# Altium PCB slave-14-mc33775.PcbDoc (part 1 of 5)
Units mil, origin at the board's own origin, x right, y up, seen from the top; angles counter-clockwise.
Board outline 6299.21 x 3937.01 mil, 6 copper layers (Top Copper, Supply, Signal Layer 1, Signal Layer 2, GND, Bot Copper), stack 69.773 mil thick; 428 components, 213 nets, 1149 pads, 1672 vias.
Unrouted connection lines stored in the file: 1.
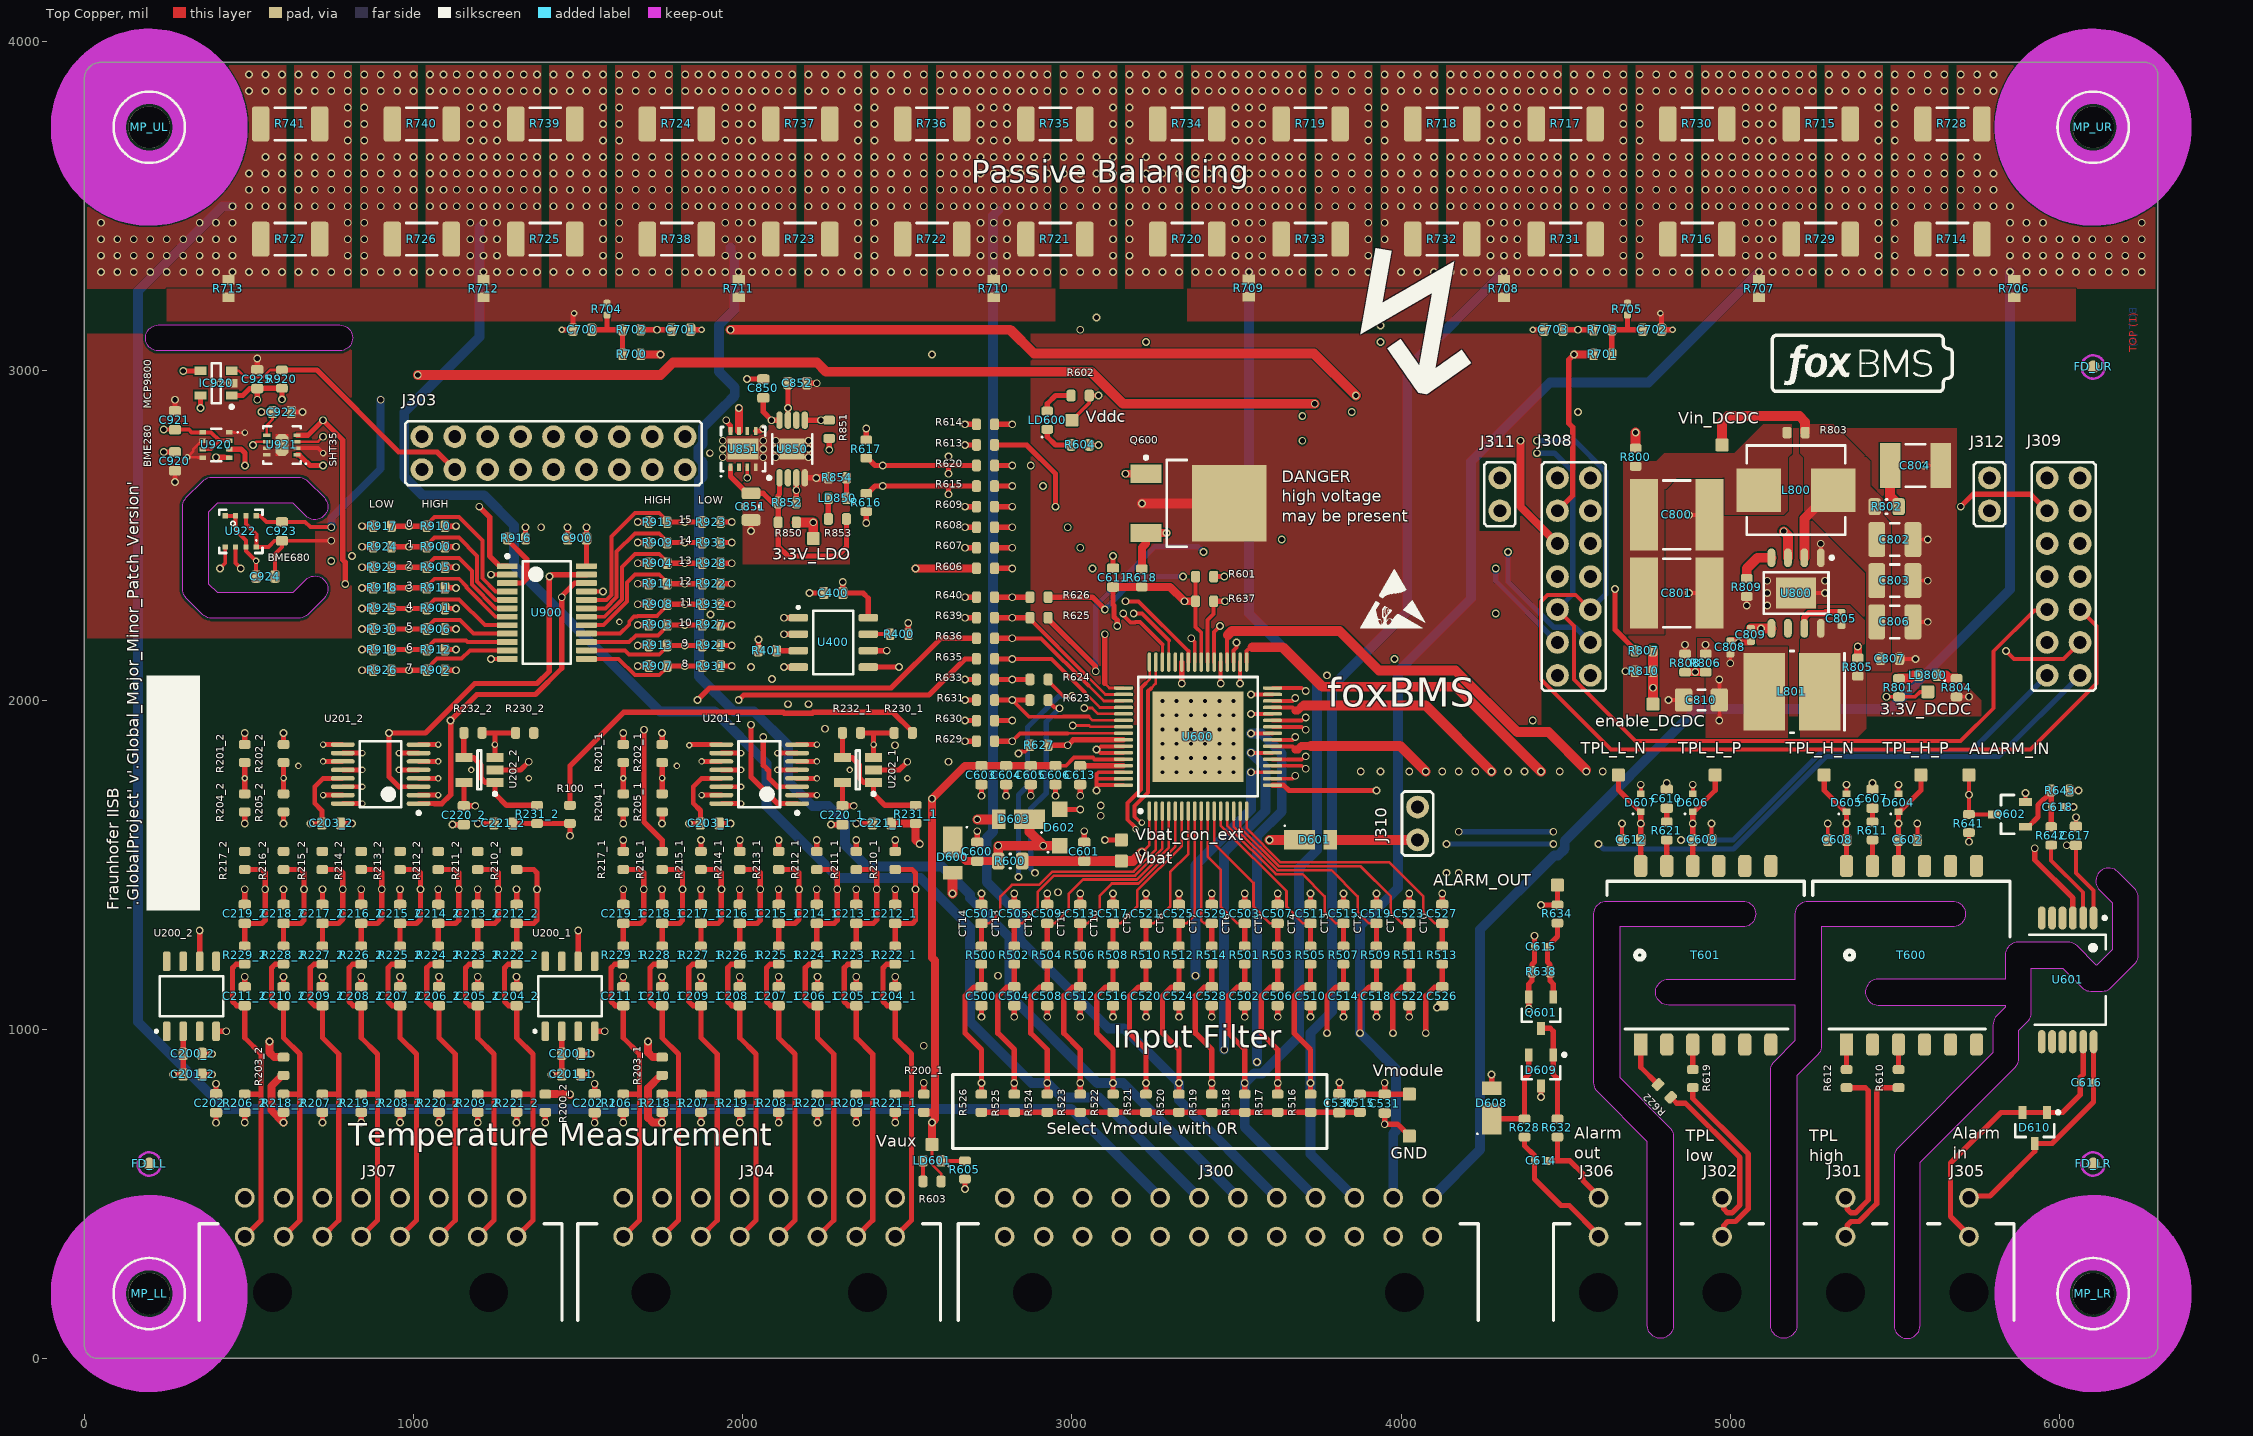
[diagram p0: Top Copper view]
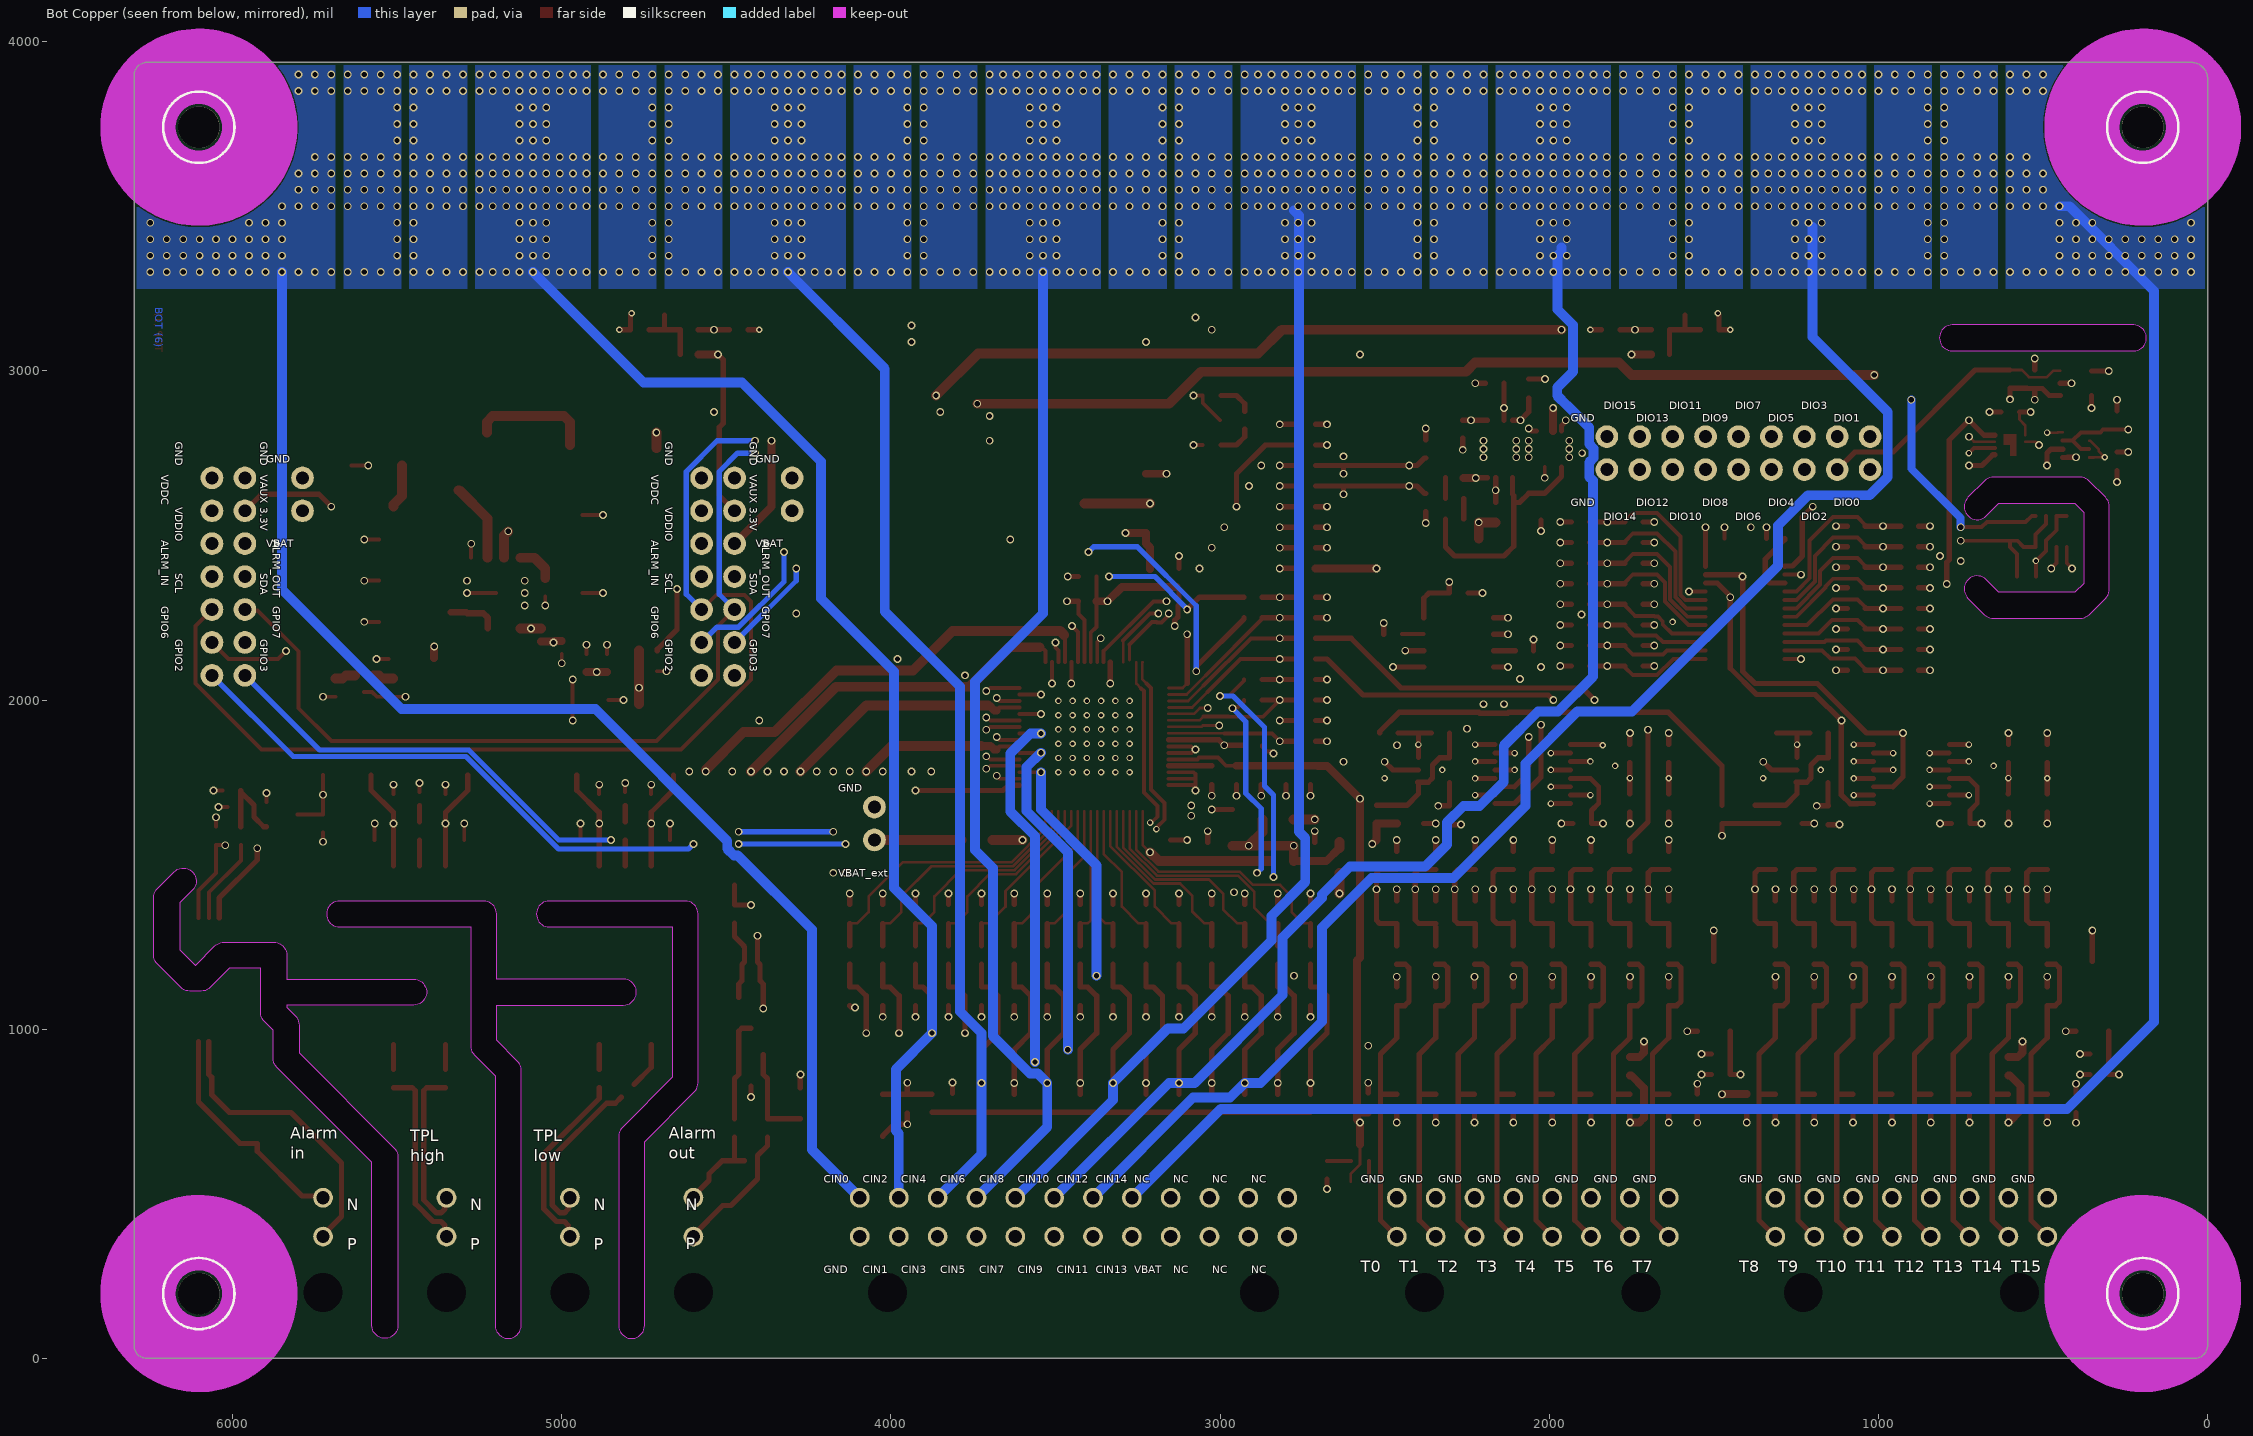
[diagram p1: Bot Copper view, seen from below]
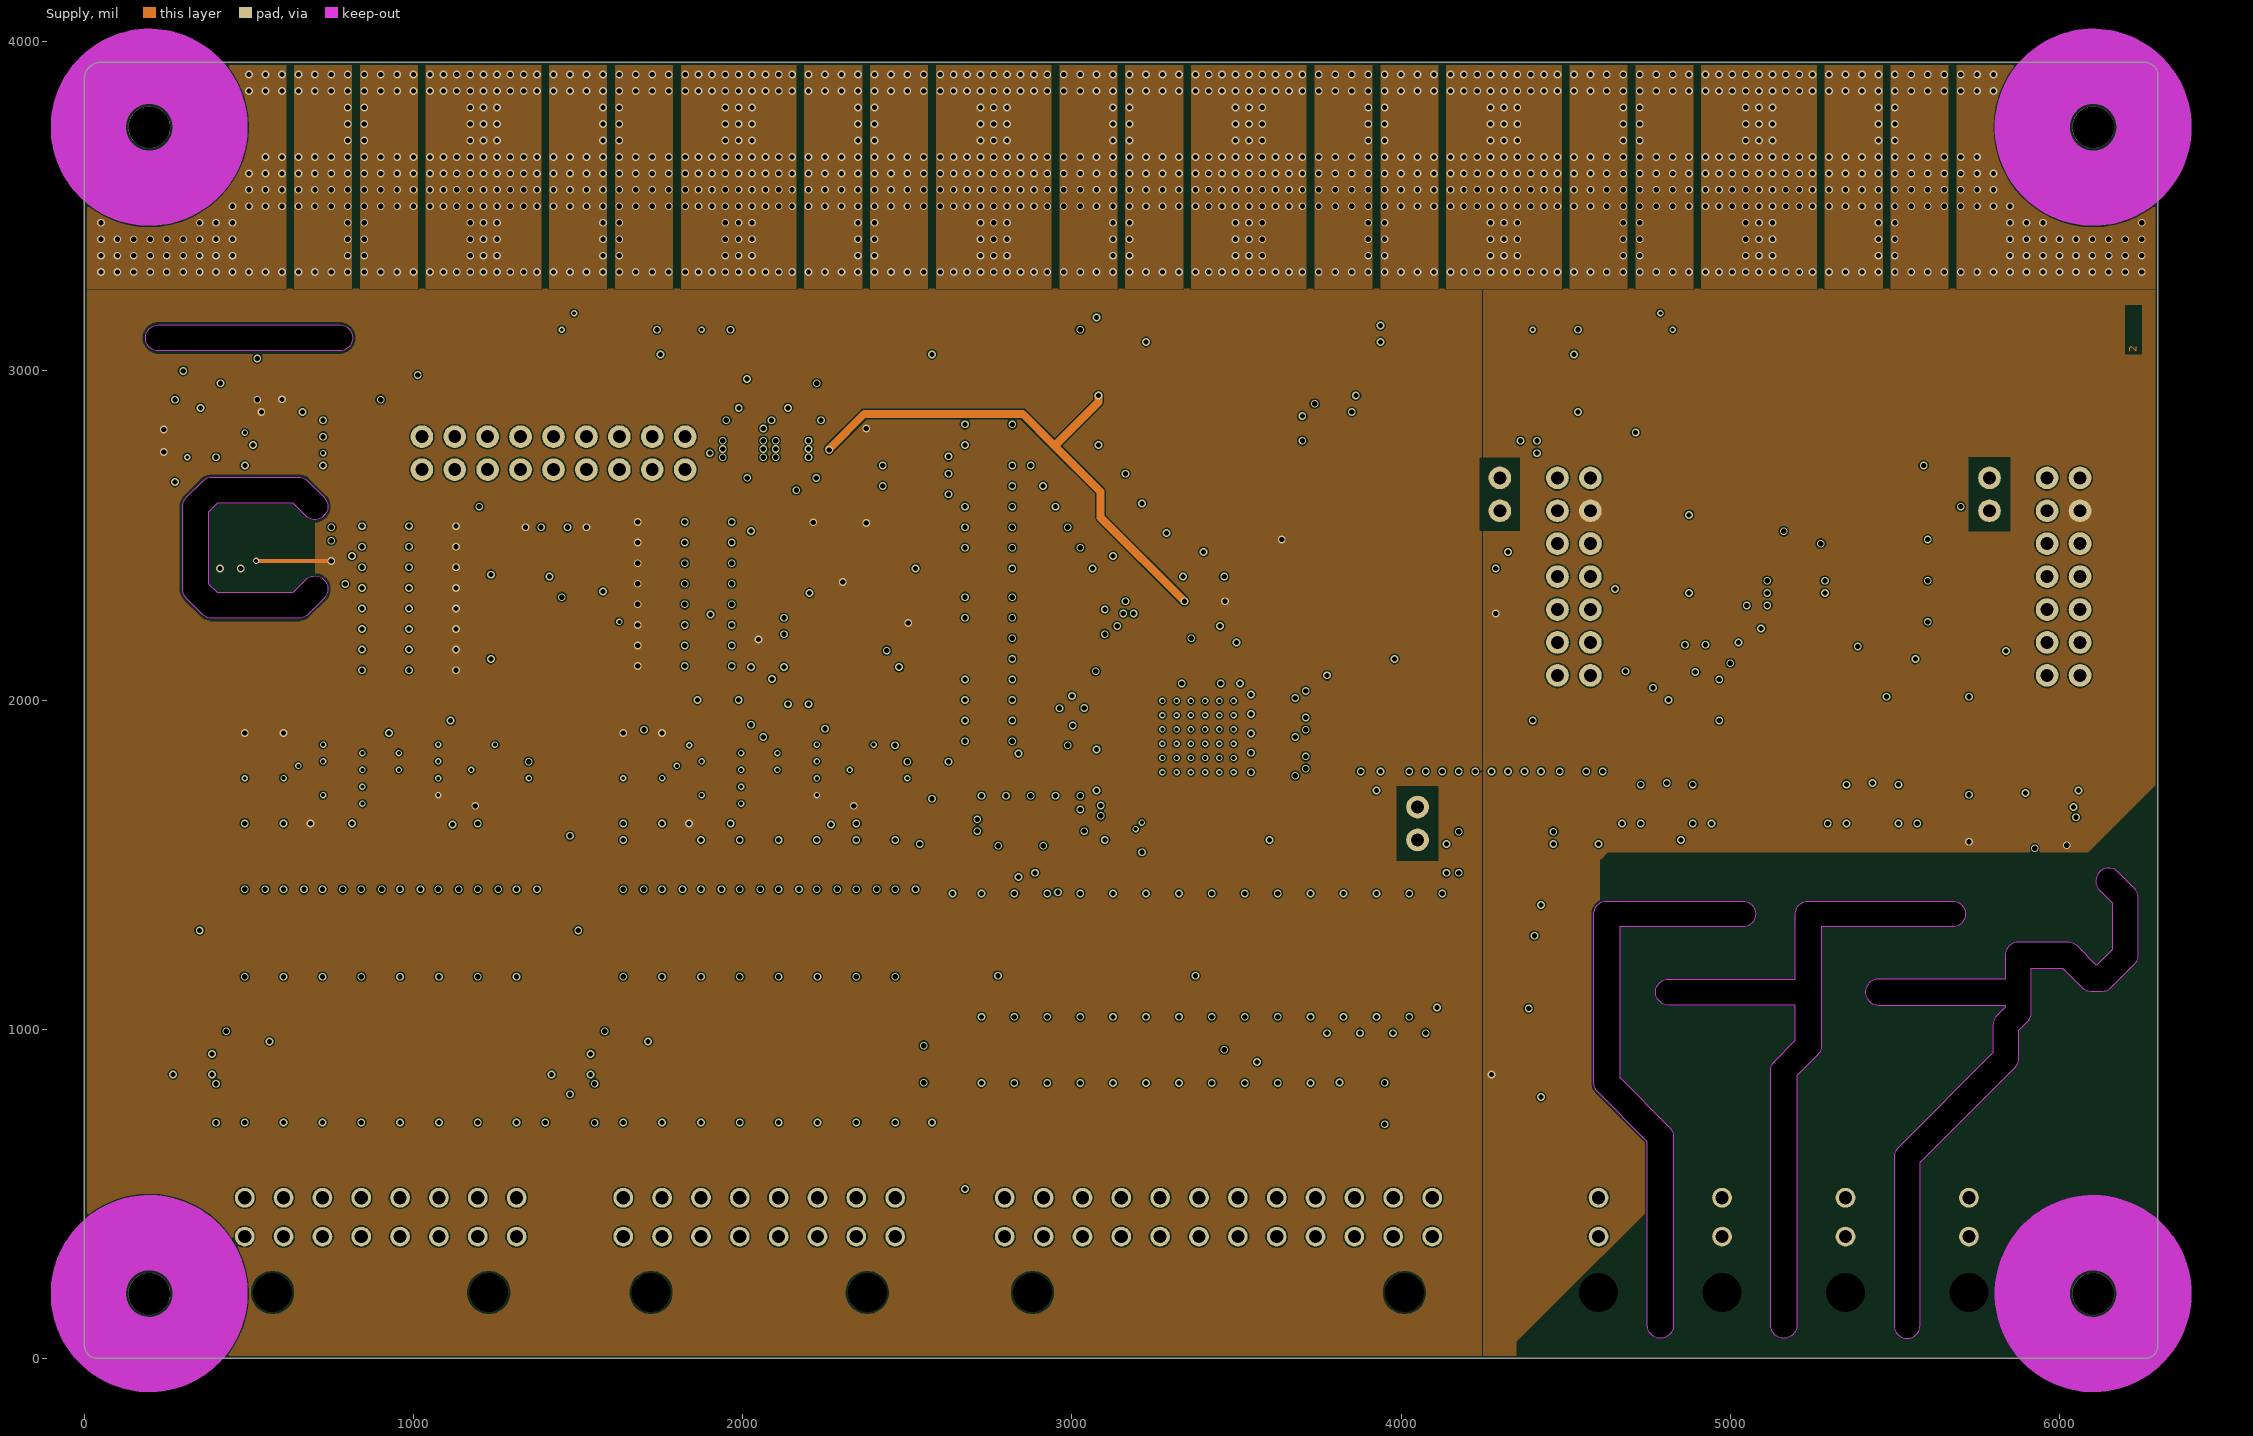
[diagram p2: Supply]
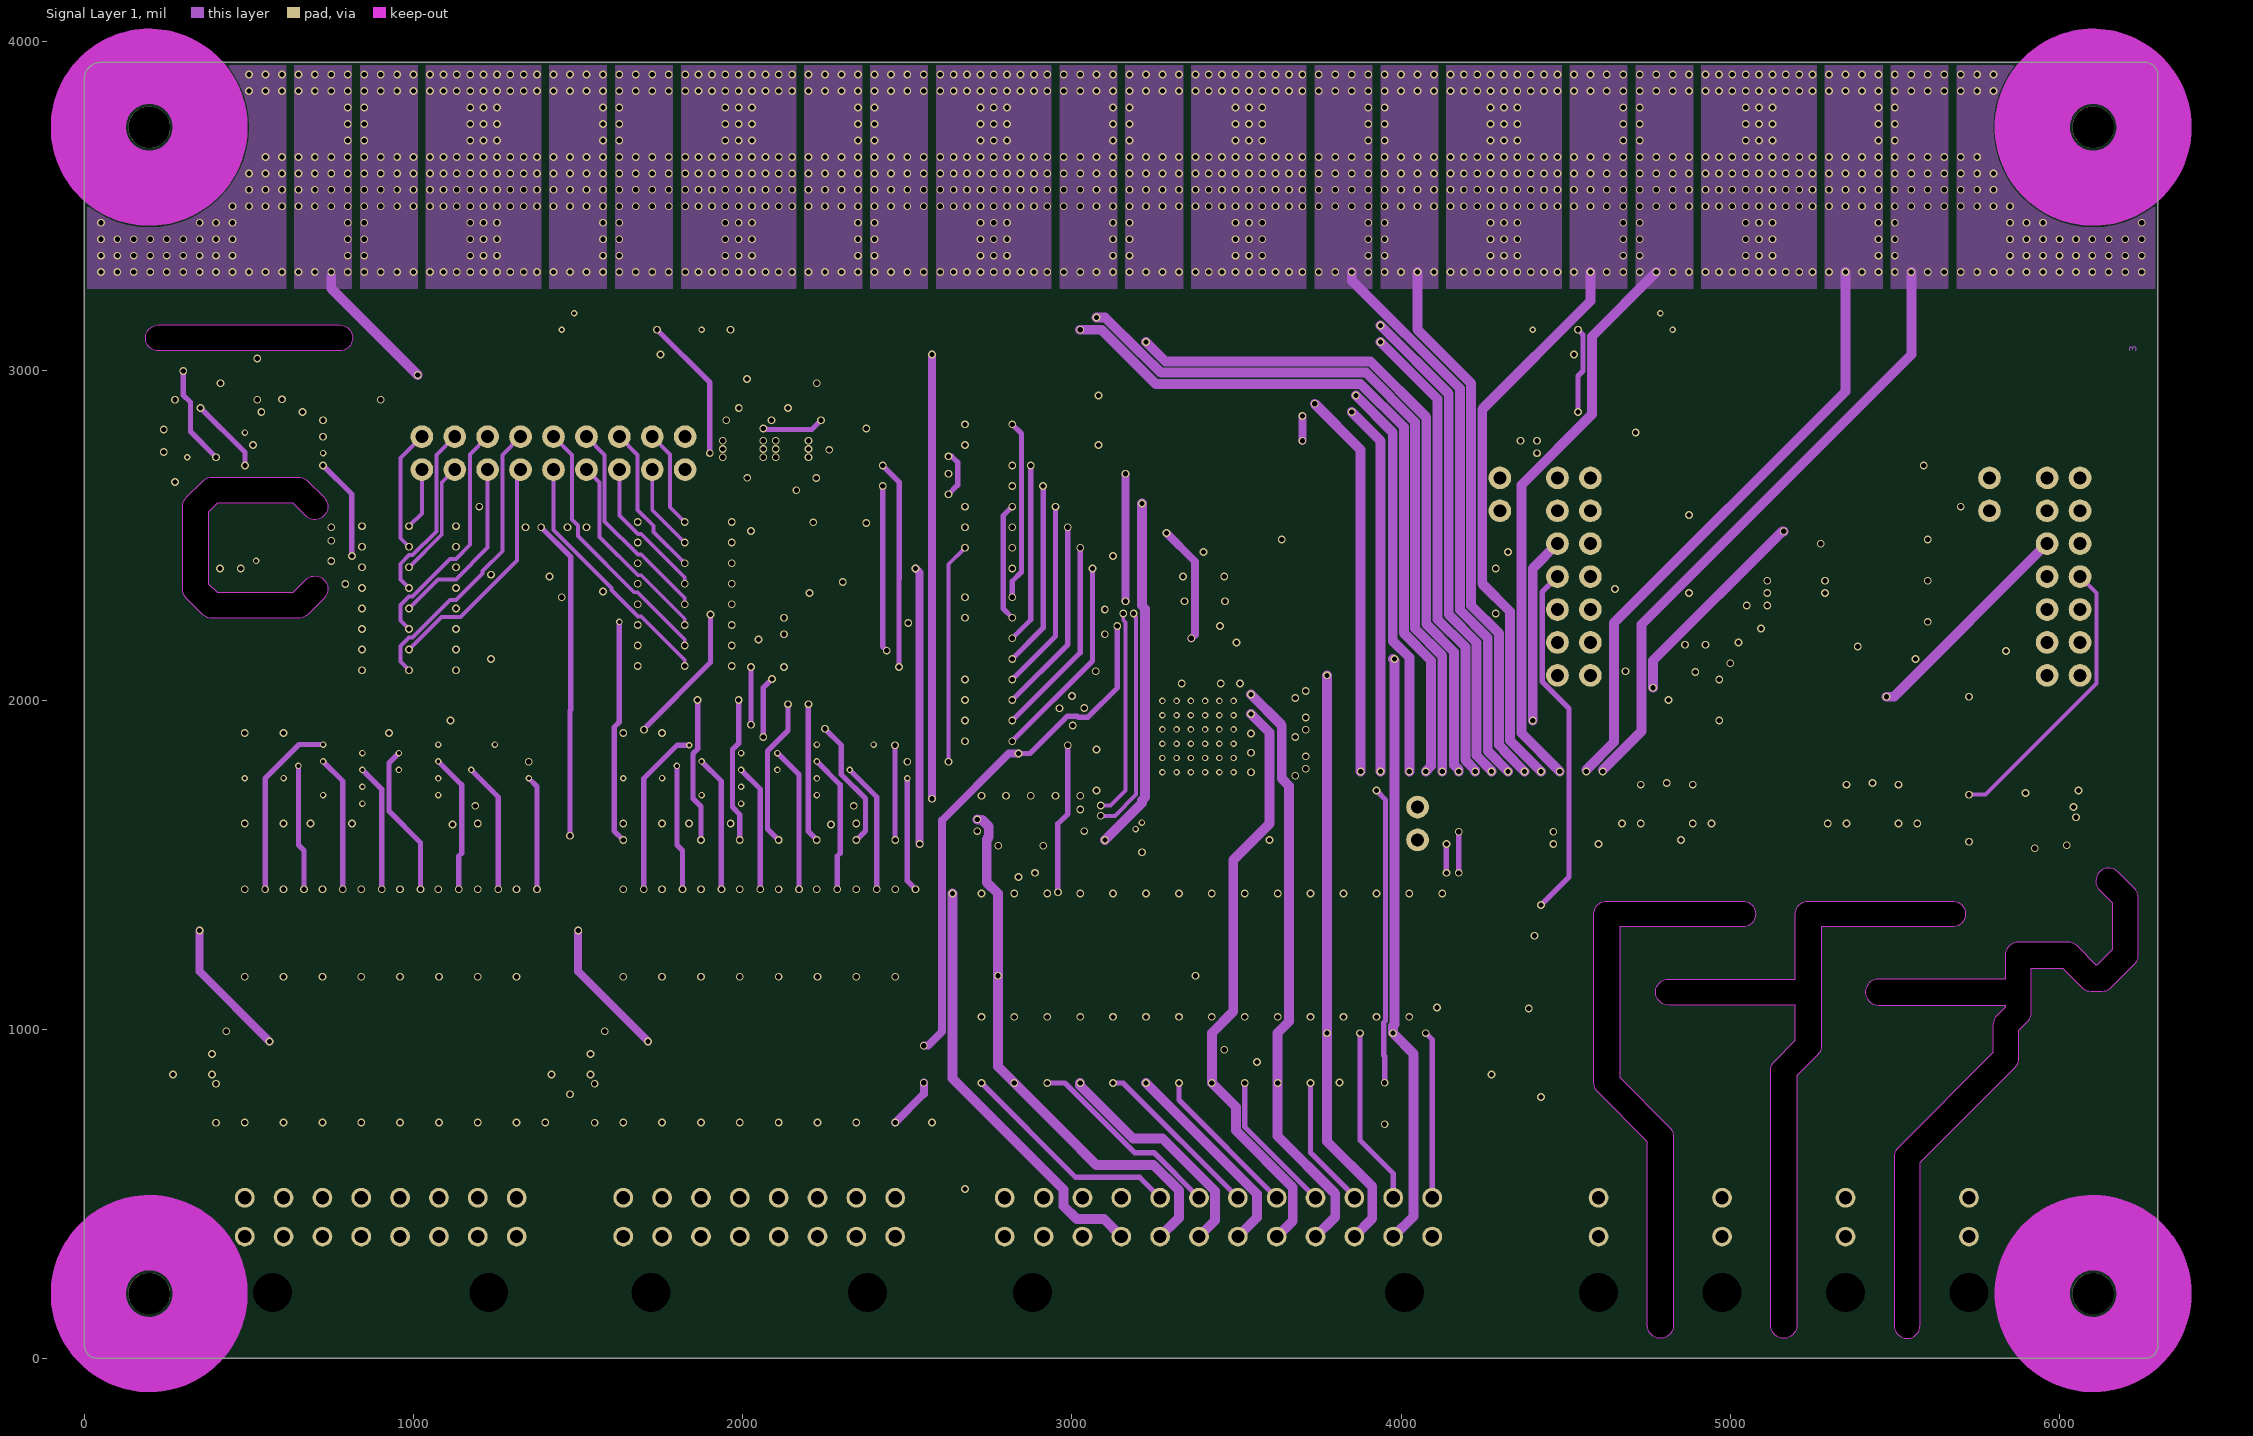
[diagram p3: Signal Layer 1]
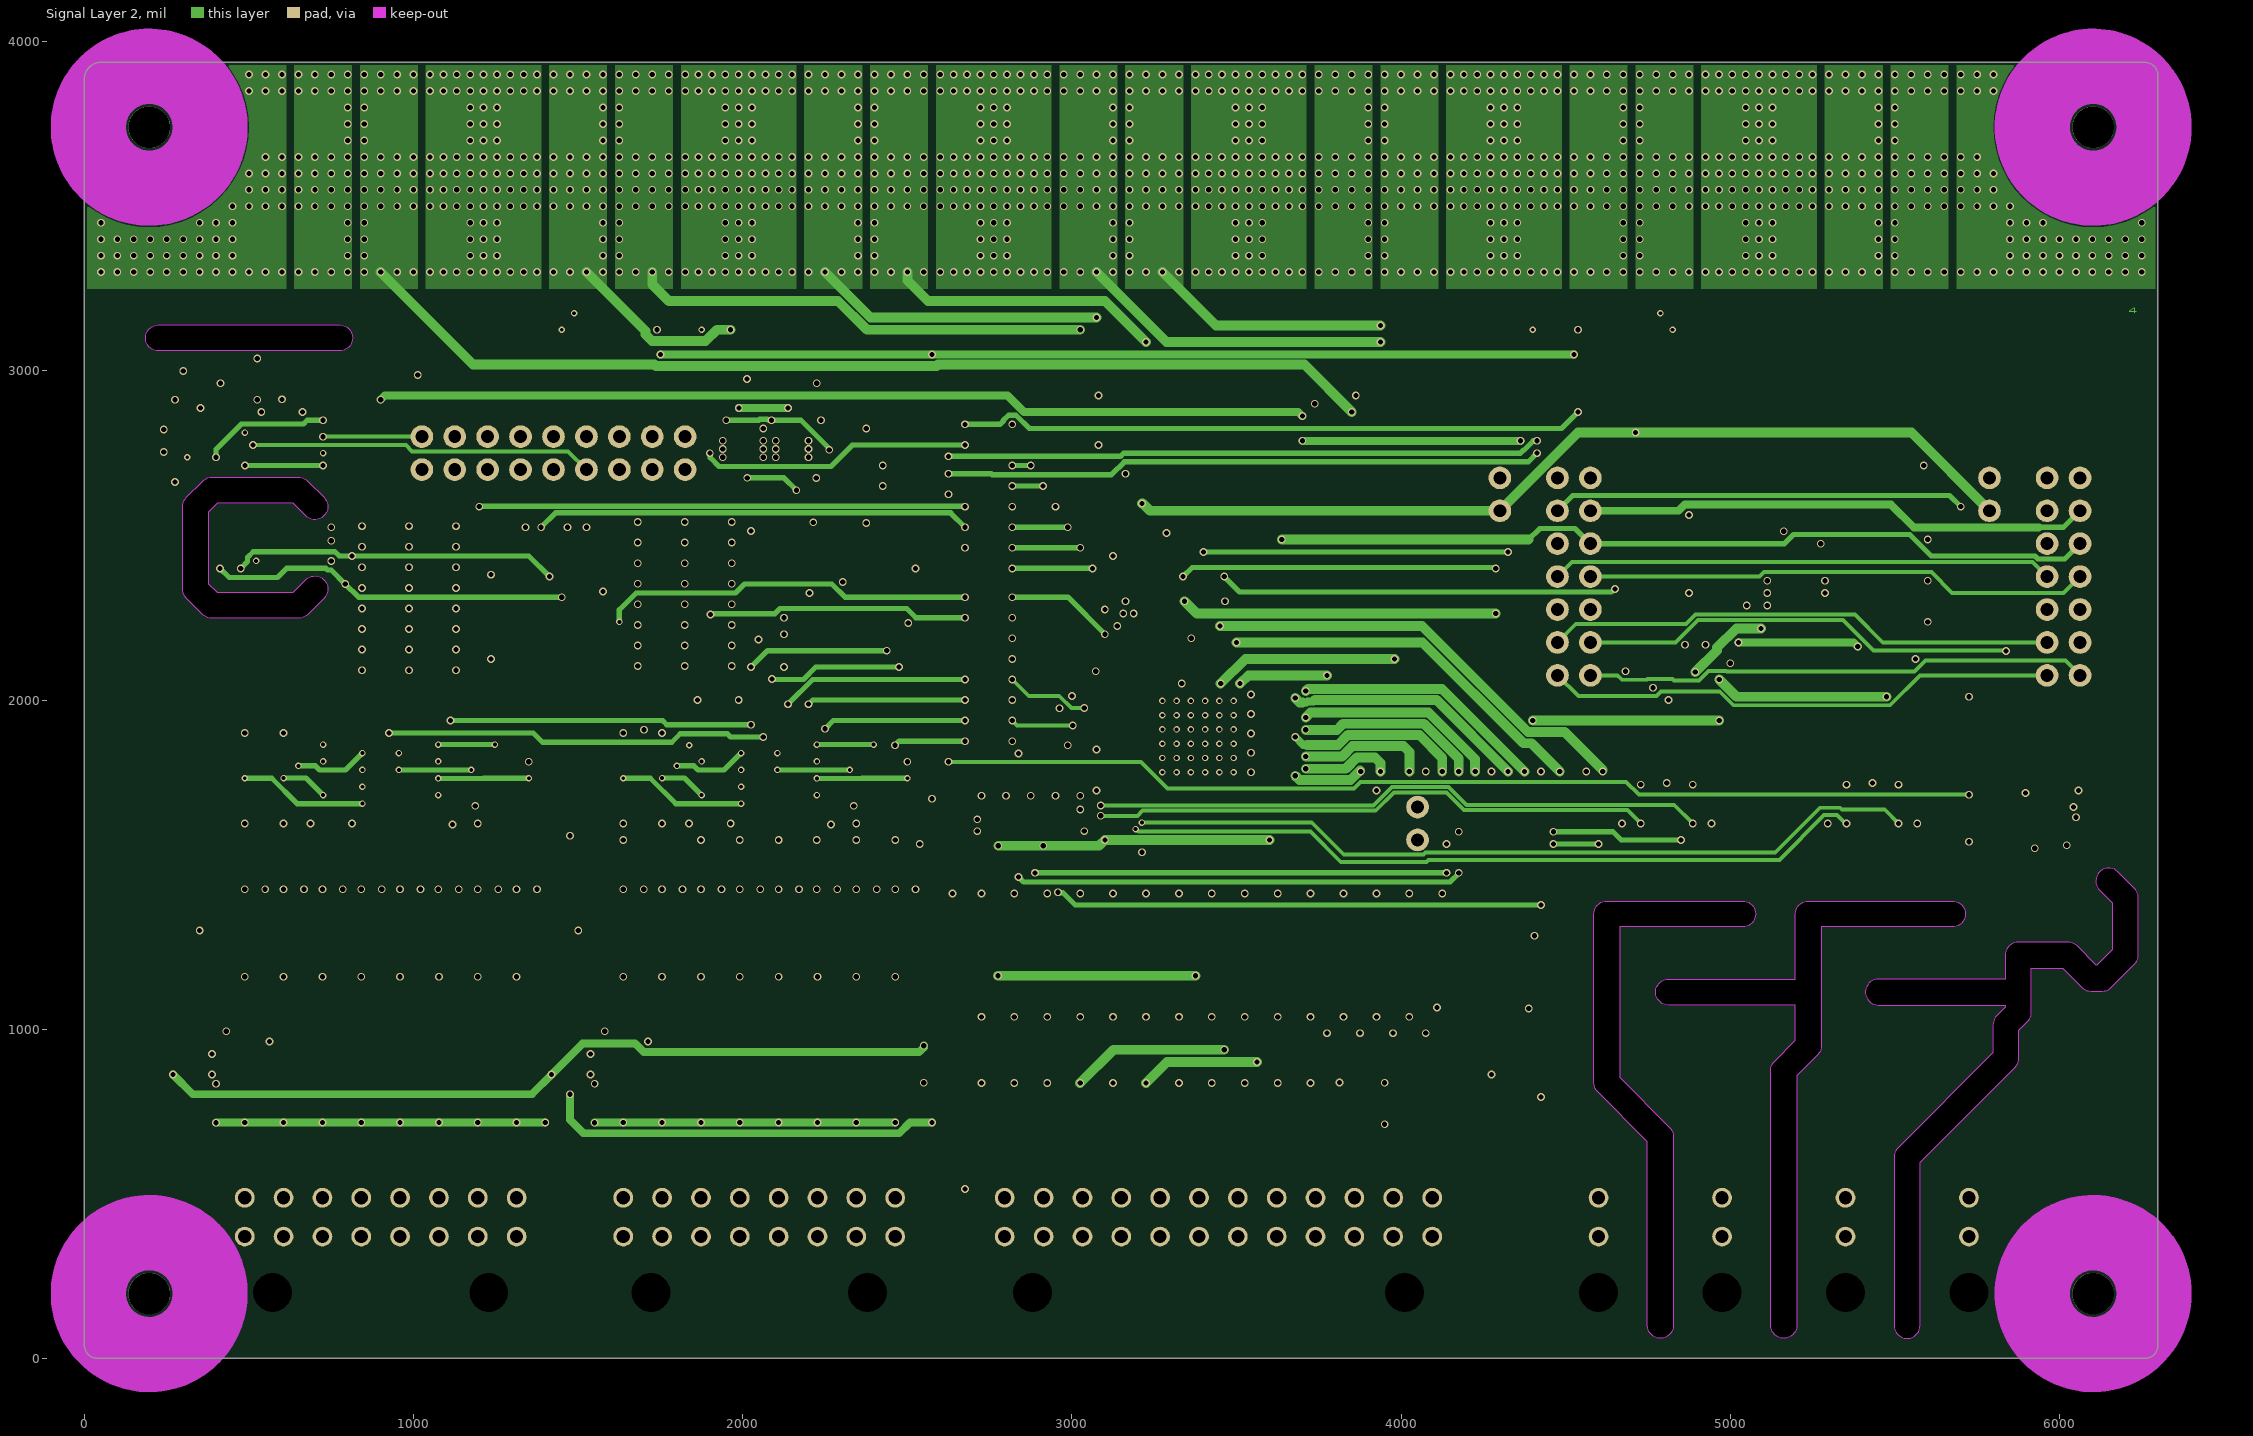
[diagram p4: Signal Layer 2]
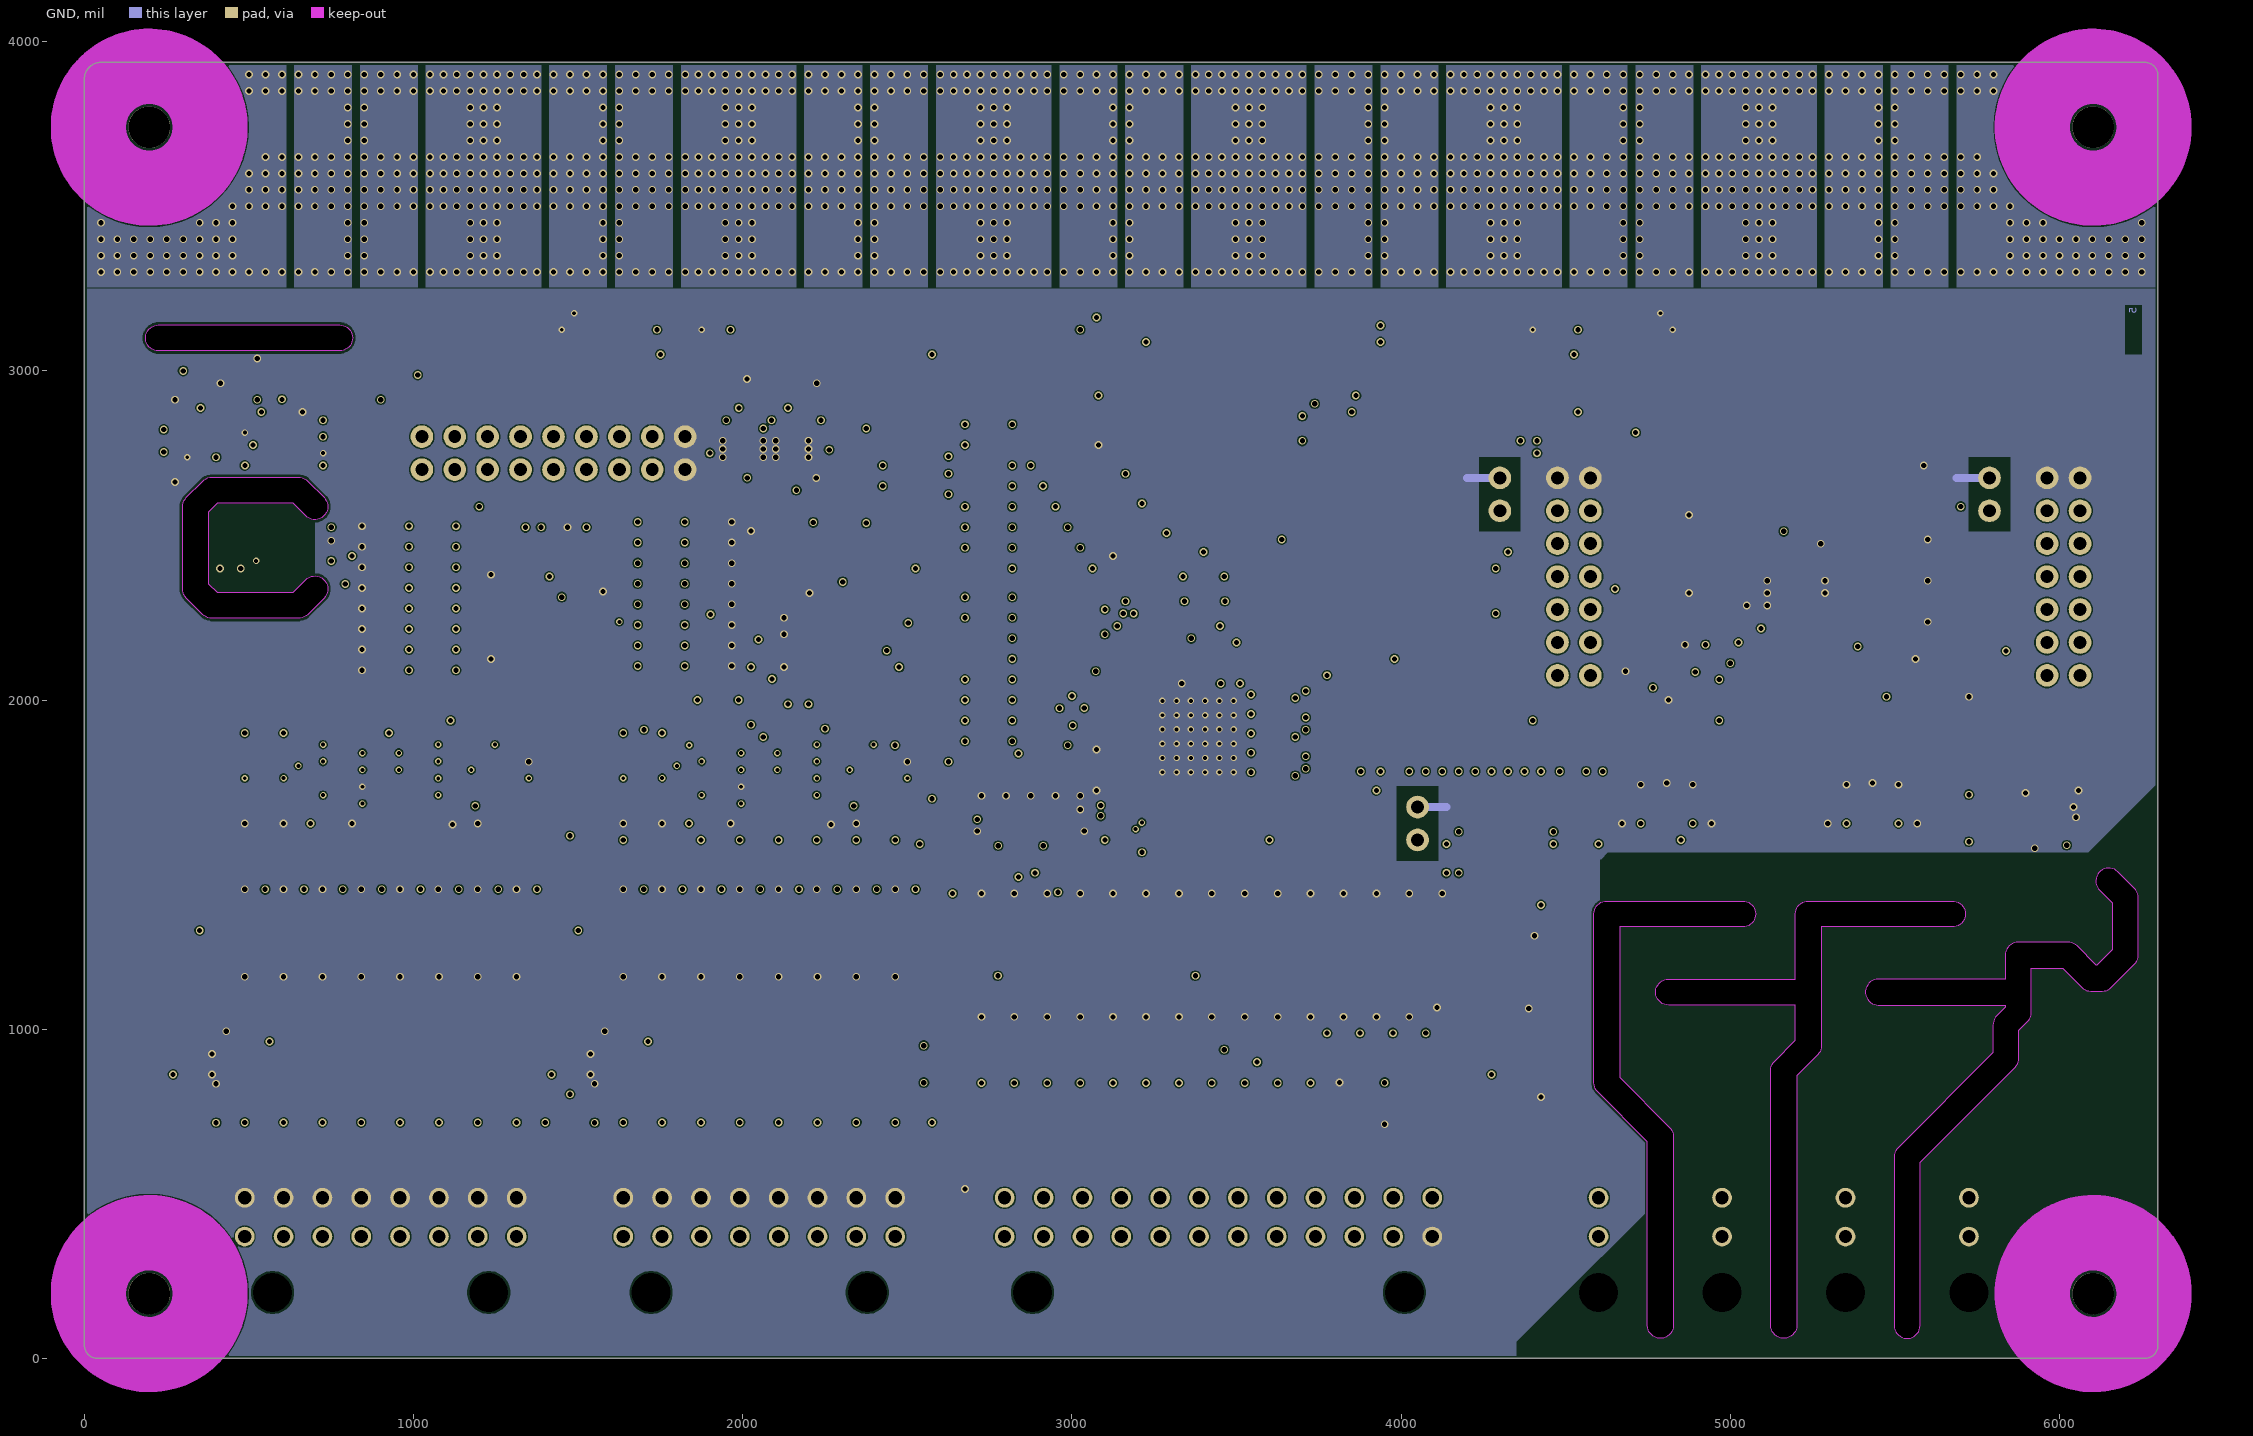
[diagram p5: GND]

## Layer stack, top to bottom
Top Solder: solder mask 0.591, Solder Resist, Dk 3.5
Top Copper: signal copper 1.378
Dielectric 1: prepreg 14.173, FR-4, Dk 4.6
Supply: signal copper 1.378
Dielectric 4: prepreg 2.8, PP-006, Dk 4.1
Signal Layer 1: signal copper 1.378
Dielectric 2: core 27.559, FR-4, Dk 4.6
Signal Layer 2: signal copper 1.378
Dielectric 5: prepreg 2.8, PP-006, Dk 4.1
GND: signal copper 1.378
Dielectric 3: prepreg 14.173, FR-4, Dk 4.6
Bot Copper: signal copper 1.378
Bottom Solder: solder mask 0.591, Solder Resist, Dk 3.5

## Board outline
0,39.37 ccw(c39.37,39.37) 39.37,0 6259.84,0 ccw(c6259.84,39.37) 6299.21,39.37 6299.21,3897.64 ccw(c6259.84,3897.64) 6259.84,3937.01 50,3937.01 ccw(c50,3887.01) 0,3887.01
cut-out: 5123.11,100 5123.11,875 cw(c5162.5,875) 5134.65,902.85 5198.11,966.31 5198.11,1073.11 4812.5,1073.11 cw(c4812.5,1112.5) 4812.5,1151.89 5198.11,1151.89 5198.11,1350 cw(c5237.5,1350) 5237.5,1389.39 5675,1389.39 cw(c5675,1350) 5714.39,1350 cw(c5675,1350) 5675,1310.61 5276.89,1310.61 5276.89,950 cw(c5237.5,950) 5265.35,922.15 5201.89,858.69 5201.89,100 cw(c5162.5,100)
cut-out: 5498.11,100 ccw(c5537.5,100) 5576.89,100 5576.89,596.19 5865.35,884.65 ccw(c5837.5,912.5) 5876.89,912.5 5876.89,996.19 5902.85,1022.15 ccw(c5875,1050) 5914.39,1050 5914.39,1185.61 6009.46,1185.61 6067.94,1127.13 ccw(c6095.79,1154.98) 6095.79,1115.6 6129.98,1115.6 ccw(c6129.98,1154.98) 6157.83,1127.13 6227.85,1197.15 ccw(c6200,1225) 6239.39,1225 6239.39,1400 ccw(c6200,1400) 6227.85,1427.85 6177.85,1477.85 ccw(c6150,1450) 6122.15,1422.15 6160.61,1383.69 6160.61,1241.31 6113.67,1194.37 6112.11,1194.37 6053.62,1252.85 ccw(c6025.77,1225) 6025.77,1264.39 ccw(c6025.39,1185.24) 6025,1264.39 5875,1264.39 ccw(c5875,1225) 5835.61,1225 5835.61,1151.89 5450,1151.89 ccw(c5450,1112.5) 5450,1073.11 5835.61,1073.11 5835.61,1066.31 5809.65,1040.35 ccw(c5837.5,1012.5) 5798.11,1012.5 5798.11,928.81 5509.65,640.35 ccw(c5537.5,612.5) 5498.11,612.5
cut-out: 4597.15,809.65 cw(c4625,837.5) 4585.61,837.5 4585.61,1350 cw(c4625,1350) 4625,1389.39 5037.5,1389.39 cw(c5037.5,1350) 5076.89,1350 cw(c5037.5,1350) 5037.5,1310.61 4664.39,1310.61 4664.39,853.81 4815.35,702.85 cw(c4787.5,675) 4826.89,675 4826.89,100 cw(c4787.5,100) 4748.11,100 4748.11,658.69
cut-out: 359.65,2259.65 309.65,2309.65 cw(c337.5,2337.5) 298.11,2337.5 298.11,2587.5 cw(c337.5,2587.5) 309.65,2615.35 359.65,2665.35 cw(c387.5,2637.5) 387.5,2676.89 650,2676.89 cw(c650,2637.5) 677.85,2665.35 727.85,2615.35 cw(c700,2587.5) 739.39,2587.5 cw(c700,2587.5) 672.15,2559.65 633.69,2598.11 403.81,2598.11 376.89,2571.19 376.89,2353.81 403.81,2326.89 633.69,2326.89 672.15,2365.35 cw(c700,2337.5) 739.39,2337.5 cw(c700,2337.5) 727.85,2309.65 677.85,2259.65 cw(c650,2287.5) 650,2248.11 387.5,2248.11 cw(c387.5,2287.5)
cut-out: 225,3060.61 cw(c225,3100) 225,3139.39 775,3139.39 cw(c775,3100) 814.39,3100 cw(c775,3100) 775,3060.61

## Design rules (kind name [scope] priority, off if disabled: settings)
AssemblyTestPointUsage [All] p1 off:
AssemblyTestpoint [(IsPad And (OnTopLayer Or OnBottomLayer)) Or (IsPad And OnMultiLayer)] p1 off: testpointundercomponent=FALSE minsize=40 maxsize=100 preferedsize=60 minholesize=0 maxholesize=40 preferedholesize=32 testpointgrid=1 usegrid=TRUE gridtolerance=0.01 allowsidetop=TRUE
BoardOutlineClearance [All] p1: gap=8 ignorepadtopadclearanceinfootprint=FALSE except(20: Arc-CavityEdge Track-CavityEdge SMDPad-CavityEdge THPad-CavityEdge Via-CavityEdge Fill-CavityEdge Poly-CavityEdge Region-CavityEdge Text-CavityEdge)
Clearance Clearance_TPL_high [InNetClass('TPL_high') vs Not InNetClass('TPL_high')] p1: gap=43.31 ignorepadtopadclearanceinfootprint=TRUE
Clearance Clearance_TPL_low [InNetClass('TPL_low') vs Not InNetClass('TPL_low')] p2: gap=43.31 ignorepadtopadclearanceinfootprint=TRUE
Clearance Clearance_Alarm_in [InNetClass('ALARM_in') vs Not InNetClass('ALARM_in')] p3: gap=43.31 ignorepadtopadclearanceinfootprint=TRUE
Clearance [All] p4: gap=4 ignorepadtopadclearanceinfootprint=TRUE except(6: Arc-Text Arc-Hole Track-Text Track-Hole SMDPad-Text SMDPad-Hole THPad-Text THPad-Hole Via-Text Via-Hole Fill-Text Fill-Hole Poly-Text Poly-Hole Region-Text Region-Hole Text-Text Text-Hole; 8: Arc-Via Track-Via SMDPad-Via THPad-Via Via-Via)
Creepage Creepage_TPL_high [InNetClass('TPL_high') vs Not InNetClass('TPL_high')] p1: checkdistance=629.92 ignoreinternallayers=FALSE
Creepage Creepage_TPL_low [InNetClass('TPL_low') vs Not InNetClass('TPL_low')] p2: checkdistance=629.92 ignoreinternallayers=FALSE
Creepage Creepage_Alarm_in [InNetClass('ALARM_in') vs Not InNetClass('ALARM_in')] p3: checkdistance=629.92 ignoreinternallayers=FALSE
Creepage [All] p4 off: checkdistance=4
DiffPairsRouting [All] p1: maxlimit=10 minlimit=10 mostfreqgap=10 toplayer_minwidth=8 toplayer_maxwidth=30 toplayer_prefwidth=15 midlayer1_minwidth=8 midlayer1_maxwidth=30 midlayer1_prefwidth=15 midlayer2_minwidth=8 midlayer2_maxwidth=30 midlayer2_prefwidth=15 midlayer3_minwidth=8 midlayer3_maxwidth=30 midlayer3_prefwidth=15 midlayer4_minwidth=8 midlayer4_maxwidth=30 midlayer4_prefwidth=15 bottomlayer_minwidth=8 bottomlayer_maxwidth=30 bottomlayer_prefwidth=15 maxuncoupledlength=500
FabricationTestpoint [All] p1: side=1 testpointundercomponent=TRUE minsize=20 maxsize=300 preferedsize=60 minholesize=0 maxholesize=40 preferedholesize=32 testpointgrid=1 allowsidetop=TRUE usegrid=FALSE gridtolerance=0.01
HoleSize [All] p1: absolutevalues=TRUE maxlimit=236 minlimit=7.87 maxpercent=80.000 minpercent=20.000
HoleToHoleClearance [All] p1: gap=6 allowstackedmicrovias=TRUE
MinimumAnnularRing [All] p1: minimumring=3.93
MinimumSolderMaskSliver [All] p1: minsoldermaskwidth=4
PlaneConnect [All] p1: planeconnectstyle=Direct reliefexpansion=20 reliefentries=4 reliefconductorwidth=10 reliefairgap=10
PolygonConnect [All] p1: connectstyle=Direct reliefconductorwidth=10 reliefentries=4 polygonreliefangle="90 Angle" airgapwidth=10
RoomDefinition U_analog_in_bank1 [InComponentClass('U_analog_in_bank1')] p1: confinementstyle=ConfineIn formatcopy=TRUE lockcomponents=FALSE outline 200.83,944.33 200.83,1255.67 446.5,1255.67 446.5,1414.13 448.46,1414.13 448.46,1899.67 717.76,1899.67 717.76,1906.06 1118.15,1906.06 1118.15,1938.54 1399.67,1938.54 1399.67,1714.72 1413.54,1714.72 1413.54,837.17 1438.54,837.17 1438.54,712.83 1351.54,712.83 440.51,712.83 440.51,710.87 359.49,710.87 359.49,821.99 264.41,821.99 264.41,944.33
RoomDefinition U_sensors [InComponentClass('U_sensors')] p2: confinementstyle=ConfineIn formatcopy=TRUE lockcomponents=FALSE outline 234.49,2660.87 234.49,2789.13 234.49,2914.13 320.12,2914.13 320.12,3038.44 484.49,3038.44 484.49,3039.13 565.51,3039.13 565.51,3037.17 638.54,3037.17 638.54,2915.51 664.13,2915.51 664.13,2847.01 686.77,2847.01 686.77,2702.99 640.51,2702.99 640.51,2448.37 614.13,2448.37 614.13,2334.49 485.87,2334.49 485.87,2430.65 393.15,2430.65 393.15,2660.87
RoomDefinition U_passive_balancing [InComponentClass('U_passive_balancing')] p3: confinementstyle=ConfineIn formatcopy=TRUE lockcomponents=FALSE outline 396.99,3187.83 396.99,3312.17 488.03,3312.17 488.03,3823.98 888.03,3823.98 5811.97,3823.98 5811.97,3312.17 5903.01,3312.17 5903.01,3187.83 4826.63,3187.83 4826.63,3084.49 4674.67,3084.49 4674.67,3011.46 1600.33,3011.46 1600.33,3084.49 1448.37,3084.49 1448.37,3187.83
RoomDefinition U_ldo [InComponentClass('U_ldo')] p4: confinementstyle=ConfineIn formatcopy=TRUE lockcomponents=FALSE outline 1919.04,2665.89 1919.04,2856.36 2021.99,2856.36 2021.99,3010.59 2103.01,3010.59 2103.01,3003.01 2229.88,3003.01 2229.88,2897.5 2231.85,2897.5 2231.85,2884.7 2301.04,2884.7 2301.04,2713.54 2349.67,2713.54 2349.67,2651.04 2352.62,2651.04 2352.62,2573.96 2349.67,2573.96 2349.67,2511.46 2245.86,2511.46 2245.86,2458.75 2182.49,2458.75 2182.49,2501.25 2073.07,2501.25 2073.07,2509.59 1974.65,2509.59 1974.65,2665.89
RoomDefinition U_input_filter [InComponentClass('U_input_filter')] p5: confinementstyle=ConfineIn formatcopy=TRUE lockcomponents=FALSE outline 2684.49,1035.87 2684.49,1164.13 2684.49,1414.13 4165.51,1414.13 4165.51,1285.87 4165.51,1035.87 3990.51,1035.87 3990.51,709.88 3909.49,709.88 3909.49,712.83 2686.46,712.83 2686.46,1035.87
RoomDefinition U_eeprom [InComponentClass('U_eeprom')] p6: confinementstyle=ConfineIn formatcopy=TRUE lockcomponents=FALSE outline 2012.83,2111.46 2012.83,2188.54 2119.33,2188.54 2119.33,2299.17 2210.87,2299.17 2210.87,2365.51 2339.13,2365.51 2339.13,2299.17 2430.67,2299.17 2430.67,2238.54 2537.17,2238.54 2537.17,2161.46 2430.67,2161.46 2430.67,2057.72 2119.33,2057.72 2119.33,2111.46
RoomDefinition U_digital_io [InComponentClass('U_digital_io')] p7: confinementstyle=ConfineIn formatcopy=TRUE lockcomponents=FALSE outline 842.76,2052.2 842.76,2566.79 1680.26,2566.79 1680.26,2579.29 1967.09,2579.29 1967.09,2064.7 1129.59,2064.7 1129.59,2052.2
RoomDefinition U_dcdc-converter [InComponentClass('U_dcdc-converter')] p8: confinementstyle=ConfineIn formatcopy=TRUE lockcomponents=FALSE outline 4673.96,2675.33 4673.96,2799.67 4943.32,2799.67 4943.32,2806.68 5137.83,2806.68 5137.83,2851.04 5262.17,2851.04 5262.17,2804 5411.77,2804 5411.77,2802.22 5691.59,2802.22 5691.59,2099.67 5726.04,2099.67 5726.04,1975.33 5551.04,1975.33 5360.89,1975.33 5360.89,1880.16 5020.02,1880.16 5020.02,1943.74 4810.96,1943.74 4810.96,1955.82 4733.37,1955.82 4733.37,2048.96 4675.33,2048.96 4675.33,2195.91 4674.94,2195.91 4674.94,2675.33
RoomDefinition U_analog_in_bank0 [InComponentClass('U_analog_in_bank0')] p9: confinementstyle=ConfineIn formatcopy=TRUE lockcomponents=FALSE outline 1350.83,944.33 1350.83,1255.67 1596.5,1255.67 1596.5,1414.13 1598.46,1414.13 1598.46,1899.67 1867.76,1899.67 1867.76,1906.06 2268.15,1906.06 2268.15,1938.54 2549.67,1938.54 2549.67,1714.72 2563.54,1714.72 2563.54,837.17 2588.54,837.17 2588.54,712.83 1590.51,712.83 1590.51,710.87 1509.49,710.87 1509.49,821.99 1414.41,821.99 1414.41,944.33
RoutingVias [All] p1: holewidth=8 width=17.72 viastyle="Through Hole" minholewidth=8 minwidth=17.72 maxholewidth=39.37 maxwidth=275.59 useviatemplates=TRUE viatemplateguid#1={F81AEFC7-3C62-4E62-9F19-F0C0822CA78E} viatemplatename#1=0.4mm_tented
SMDEntry [All] p1: side=TRUE corner=TRUE anyangle=FALSE
SMDToCorner [All] p1: distance=40000
SilkToSolderMaskClearance [IsPad] p1: minsilkscreentomaskgap=4 clearancetoexposedcopper=FALSE
SolderMaskExpansion SolderMaskExpansion_VIAs [IsVia] p1: expansion=-393.7 istentingtop=FALSE // Cover all Vias
SolderMaskExpansion [All] p2: expansion=2 istentingtop=FALSE
SupplyNets "Schematic Supply Nets_10" [InNet('VBAT')] p1: voltage=0.000
SupplyNets "Schematic Supply Nets_9" [InNet('VAUX')] p2: voltage=0.000
SupplyNets "Schematic Supply Nets_8" [InNet('VDDIO')] p3: voltage=0.000
SupplyNets "Schematic Supply Nets_7" [InNet('VBAT_con')] p4: voltage=0.000
SupplyNets "Schematic Supply Nets_6" [InNet('VMODULE')] p5: voltage=0.000
SupplyNets "Schematic Supply Nets_5" [InNet('VDDA')] p6: voltage=0.000
SupplyNets "Schematic Supply Nets_4" [InNet('VBAT_ext')] p7: voltage=0.000
SupplyNets "Schematic Supply Nets_3" [InNet('GND')] p8: voltage=0.000
SupplyNets "Schematic Supply Nets_2" [InNet('VDDC')] p9: voltage=0.000
SupplyNets "Schematic Supply Nets_1" [InNet('+3.3V')] p10: voltage=0.000
SupplyNets "Schematic Supply Nets" [InNet('VBAT_con_ext')] p11: voltage=0.000
UnRoutedNet [All] p1: checkbadconnections=TRUE
UnpouredPolygon UnpouredPolygon_1 [All] p1:
Width [All] p1: maxlimit=60 minlimit=4 preferedwidth=6
19 further rules are at their usual default settings.

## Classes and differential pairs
net class TPL_low: NetR619_1 NetR622_1 TPL_L._N TPL_L._P
net class TPL_high: NetR610_1 NetR612_1 TPL_H._N TPL_H._P
net class ALARM_in: AL_IN._N AL_IN._P Gnd2_unused Gnd22_unused Vdd2_unused Vout_unused
component class U_ldo: 3.3V_LDO C850 C851 C852 LD850 R850 R851 R852 R853 R854 U850 U851
component class slave-14-mc33775: MP_LL MP_LR MP_UL MP_UR R100
channel class analog_in: U_analog_in_bank0 U_analog_in_bank1
net class T_FILT[0..7]: T_FILT0 T_FILT1 T_FILT2 T_FILT3 T_FILT4 T_FILT5 T_FILT6 T_FILT7
net class DIGITAL-IO_[0..15]: DIGITAL-IO_0 DIGITAL-IO_1 DIGITAL-IO_2 DIGITAL-IO_3 DIGITAL-IO_4 DIGITAL-IO_5 DIGITAL-IO_6 DIGITAL-IO_7 DIGITAL-IO_8 DIGITAL-IO_9 DIGITAL-IO_10 DIGITAL-IO_11 DIGITAL-IO_12 DIGITAL-IO_13 DIGITAL-IO_14 DIGITAL-IO_15
component class U_sensors: C920 C921 C922 C923 C924 C925 IC920 R920 U920 U921 U922
component class U_digital_io: C900 R900 R901 R902 R903 R904 R905 R906 R907 R908 R909 R910 R911 R912 R913 R914 R915 R916 R917 R918 R919 R921 R922 R923 R924 R925 R926 R927 R928 R929 R930 R931 R932 R933 U900
component class U_dcdc-converter: 3.3V_DCDC C800 C801 C802 C803 C804 C805 C806 C807 C808 C809 C810 enable_DCDC L800 L801 LD800 R800 R801 R802 R803 R804 R805 R806 R807 R808 R809 R810 U800 Vin_DCDC
component class U_analog_in_bank1: C200_2 C201_2 C202_2 C203_2 C204_2 C205_2 C206_2 C207_2 C208_2 C209_2 C210_2 C211_2 C212_2 C213_2 C214_2 C215_2 C216_2 C217_2 C218_2 C219_2 C220_2 C221_2 R200_2 R201_2 R202_2 R203_2 R204_2 R205_2 R206_2 R207_2 R208_2 R209_2 R210_2 R211_2 R212_2 R213_2 R214_2 R215_2 R216_2 R217_2 R218_2 R219_2 R220_2 R221_2 R222_2 R223_2 R224_2 R225_2 R226_2 R227_2 R228_2 R229_2 R230_2 R231_2 R232_2 U200_2 U201_2 U202_2
differential pair class TPL_H: TPL_H.
net class T-SENSOR_[0..15]: T-SENSOR_0 T-SENSOR_1 T-SENSOR_2 T-SENSOR_3 T-SENSOR_4 T-SENSOR_5 T-SENSOR_6 T-SENSOR_7 T-SENSOR_8 T-SENSOR_9 T-SENSOR_10 T-SENSOR_11 T-SENSOR_12 T-SENSOR_13 T-SENSOR_14 T-SENSOR_15
net class GPIO[0..7]: GPIO0 GPIO1 GPIO2 GPIO3 GPIO4 GPIO5 GPIO6 GPIO7
net class CT[0..14]: CT0 CT1 CT2 CT3 CT4 CT5 CT6 CT7 CT8 CT9 CT10 CT11 CT12 CT13 CT14
net class CIN[0..14]: CIN0 CIN1 CIN2 CIN3 CIN4 CIN5 CIN6 CIN7 CIN8 CIN9 CIN10 CIN11 CIN12 CIN13 CIN14
net class BAL_NTC[0..1]: BAL_NTC0 BAL_NTC1
component class U_passive_balancing: C700 C701 C702 C703 R700 R701 R702 R703 R704 R705 R706 R707 R708 R709 R710 R711 R712 R713 R714 R715 R716 R717 R718 R719 R720 R721 R722 R723 R724 R725 R726 R727 R728 R729 R730 R731 R732 R733 R734 R735 R736 R737 R738 R739 R740 R741
component class U_mc33775: ALARM_IN ALARM_OUT C600 C601 C602 C603 C604 C605 C606 C607 C608 C609 C610 C611 C612 C613 C614 C615 C616 C617 C618 D600 D601 D602 D603 D604 D605 D606 D607 D608 D609 D610 GND LD600 LD601 Q600 Q601 Q602 R600 R601 R602 R603 R604 R605 R606 R607 R608 R609 R610 R611 R612 R613 R614 R615 R616 R617 R618 R619 R620 R621 R622 R623 R624 R625 R626 R627 R628 R629 R630 R631 R632 R633 R634 R635 R636 R637 R638 R639 R640 R641 R642 R643 T600 T601 TPL_H_N TPL_H_P TPL_L_N TPL_L_P U600 U601 Vaux Vbat Vbat_con_ext Vddc Vmodule
component class U_input_filter: C500 C501 C502 C503 C504 C505 C506 C507 C508 C509 C510 C511 C512 C513 C514 C515 C516 C517 C518 C519 C520 C521 C522 C523 C524 C525 C526 C527 C528 C529 C530 C531 R500 R501 R502 R503 R504 R505 R506 R507 R508 R509 R510 R511 R512 R513 R514 R515 R516 R517 R518 R519 R520 R521 R522 R523 R524 R525 R526
component class U_eeprom: C400 R400 R401 U400
component class U_connectors: J300 J301 J302 J303 J304 J305 J306 J307 J308 J309 J310 J311 J312
component class U_analog_in_bank0: C200_1 C201_1 C202_1 C203_1 C204_1 C205_1 C206_1 C207_1 C208_1 C209_1 C210_1 C211_1 C212_1 C213_1 C214_1 C215_1 C216_1 C217_1 C218_1 C219_1 C220_1 C221_1 R200_1 R201_1 R202_1 R203_1 R204_1 R205_1 R206_1 R207_1 R208_1 R209_1 R210_1 R211_1 R212_1 R213_1 R214_1 R215_1 R216_1 R217_1 R218_1 R219_1 R220_1 R221_1 R222_1 R223_1 R224_1 R225_1 R226_1 R227_1 R228_1 R229_1 R230_1 R231_1 R232_1 U200_1 U201_1 U202_1
differential pair TPL_L.: +TPL_L._P -TPL_L._N
differential pair TPL_H.: +TPL_H._P -TPL_H._N
differential pair RXTXL: +RXTXL_P -RXTXL_N
differential pair RXTXH: +RXTXH_P -RXTXH_N

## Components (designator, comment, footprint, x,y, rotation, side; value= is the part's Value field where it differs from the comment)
3.3V_DCDC "Testpoint_Square" Testpoint_S1 5600,2025 r90 top
3.3V_LDO "Testpoint_Square" Testpoint_S1 2214.17,2490.43 r90 top
ALARM_IN "Testpoint_Square" Testpoint_S1 5725,1772.24 r90 top
ALARM_OUT "Testpoint_Square" Testpoint_S1 4475,1437.5 r90 top
C200_1 "1u/35V" CAPC1608X08N 1478.54,925 r180 top (schematic designator C200)
C200_2 "1u/35V" CAPC1608X08N 328.54,925 r180 top (schematic designator C200)
C201_1 "100n/100V" CAPC1608X08N 1478.54,862.5 r180 top (schematic designator C201)
C201_2 "100n/100V" CAPC1608X08N 328.54,862.5 r180 top (schematic designator C201)
C202_1 "10n/100V" CAPC1608X08N 1550,775 r270 top (schematic designator C202)
C202_2 "10n/100V" CAPC1608X08N 400,775 r270 top (schematic designator C202)
C203_1 "1u/35V" CAPC1608X08N 1900,1625 r180 top (schematic designator C203)
C203_2 "1u/35V" CAPC1608X08N 750,1625 r180 top (schematic designator C203)
C204_1 "10n/100V" CAPC1608X08N 2462.99,1100 r270 top (schematic designator C204)
C204_2 "10n/100V" CAPC1608X08N 1312.99,1100 r270 top (schematic designator C204)
C205_1 "10n/100V" CAPC1608X08N 2345,1100 r270 top (schematic designator C205)
C205_2 "10n/100V" CAPC1608X08N 1195,1100 r270 top (schematic designator C205)
C206_1 "10n/100V" CAPC1608X08N 2227.01,1100 r270 top (schematic designator C206)
C206_2 "10n/100V" CAPC1608X08N 1077.01,1100 r270 top (schematic designator C206)
C207_1 "10n/100V" CAPC1608X08N 2109.02,1100 r270 top (schematic designator C207)
C207_2 "10n/100V" CAPC1608X08N 959.02,1100 r270 top (schematic designator C207)
C208_1 "10n/100V" CAPC1608X08N 1990.98,1100 r270 top (schematic designator C208)
C208_2 "10n/100V" CAPC1608X08N 840.98,1100 r270 top (schematic designator C208)
C209_1 "10n/100V" CAPC1608X08N 1872.99,1100 r270 top (schematic designator C209)
C209_2 "10n/100V" CAPC1608X08N 722.99,1100 r270 top (schematic designator C209)
C210_1 "10n/100V" CAPC1608X08N 1755,1100 r270 top (schematic designator C210)
C210_2 "10n/100V" CAPC1608X08N 605,1100 r270 top (schematic designator C210)
C211_1 "10n/100V" CAPC1608X08N 1637.01,1100 r270 top (schematic designator C211)
C211_2 "10n/100V" CAPC1608X08N 487.01,1100 r270 top (schematic designator C211)
C212_1 "100n/100V" CAPC1608X08N 2462.99,1350 r270 top (schematic designator C212)
C212_2 "100n/100V" CAPC1608X08N 1312.99,1350 r270 top (schematic designator C212)
C213_1 "100n/100V" CAPC1608X08N 2345,1350 r270 top (schematic designator C213)
C213_2 "100n/100V" CAPC1608X08N 1195,1350 r270 top (schematic designator C213)
C214_1 "100n/100V" CAPC1608X08N 2225,1350 r270 top (schematic designator C214)
C214_2 "100n/100V" CAPC1608X08N 1075,1350 r270 top (schematic designator C214)
C215_1 "100n/100V" CAPC1608X08N 2109.02,1350 r270 top (schematic designator C215)
C215_2 "100n/100V" CAPC1608X08N 959.02,1350 r270 top (schematic designator C215)
C216_1 "100n/100V" CAPC1608X08N 1990.98,1350 r270 top (schematic designator C216)
C216_2 "100n/100V" CAPC1608X08N 840.98,1350 r270 top (schematic designator C216)
C217_1 "100n/100V" CAPC1608X08N 1872.99,1350 r270 top (schematic designator C217)
C217_2 "100n/100V" CAPC1608X08N 722.99,1350 r270 top (schematic designator C217)
C218_1 "100n/100V" CAPC1608X08N 1755,1350 r270 top (schematic designator C218)
C218_2 "100n/100V" CAPC1608X08N 605,1350 r270 top (schematic designator C218)
C219_1 "100n/100V" CAPC1608X08N 1637.01,1350 r270 top (schematic designator C219)
C219_2 "100n/100V" CAPC1608X08N 487.01,1350 r270 top (schematic designator C219)
C220_1 "1u/35V" CAPC1608X08N 2302.76,1650 r90 top (schematic designator C220)
C220_2 "1u/35V" CAPC1608X08N 1152.76,1650 r90 top (schematic designator C220)
C221_1 "100n/100V" CAPC1608X08N 2422.64,1625 r0 top (schematic designator C221)
C221_2 "100n/100V" CAPC1608X08N 1272.64,1625 r0 top (schematic designator C221)
C400 "100n/100V" CAPC1608X08N 2275,2325 r0 top
C500 "47n/100V" CAPC1608X08N 2725,1100 r90 top
C501 "47n/100V" CAPC1608X08N 2725,1350 r270 top
C502 "47n/100V" CAPC1608X08N 3525,1100 r90 top
C503 "47n/100V" CAPC1608X08N 3525,1350 r270 top
C504 "47n/100V" CAPC1608X08N 2825,1100 r90 top
C505 "47n/100V" CAPC1608X08N 2825,1350 r270 top
C506 "47n/100V" CAPC1608X08N 3625,1100 r90 top
C507 "47n/100V" CAPC1608X08N 3625,1350 r270 top
C508 "47n/100V" CAPC1608X08N 2925,1100 r90 top
C509 "47n/100V" CAPC1608X08N 2925,1350 r270 top
C510 "47n/100V" CAPC1608X08N 3725,1100 r90 top
C511 "47n/100V" CAPC1608X08N 3725,1350 r270 top
C512 "47n/100V" CAPC1608X08N 3025,1100 r90 top
C513 "47n/100V" CAPC1608X08N 3025,1350 r270 top
C514 "47n/100V" CAPC1608X08N 3825,1100 r90 top
C515 "47n/100V" CAPC1608X08N 3825,1350 r270 top
C516 "47n/100V" CAPC1608X08N 3125,1100 r90 top
C517 "47n/100V" CAPC1608X08N 3125,1350 r270 top
C518 "47n/100V" CAPC1608X08N 3925,1100 r90 top
C519 "47n/100V" CAPC1608X08N 3925,1350 r270 top
C520 "47n/100V" CAPC1608X08N 3225,1100 r90 top
C521 "47n/100V" CAPC1608X08N 3225,1350 r270 top
C522 "47n/100V" CAPC1608X08N 4025,1100 r90 top
C523 "47n/100V" CAPC1608X08N 4025,1350 r270 top
C524 "47n/100V" CAPC1608X08N 3325,1100 r90 top
C525 "47n/100V" CAPC1608X08N 3325,1350 r270 top
C526 "47n/100V" CAPC1608X08N 4125,1100 r90 top
C527 "47n/100V" CAPC1608X08N 4125,1350 r270 top
C528 "47n/100V" CAPC1608X08N 3425,1100 r90 top
C529 "47n/100V" CAPC1608X08N 3425,1350 r270 top
C530 "47n/100V" CAPC1608X08N 3812.5,775 r270 top
C531 "47n/100V" CAPC1608X08N 3950,774.02 r90 top
C600 "47n/100V" CAPC1608X08N 2712.5,1539.17 r270 top
C601 "100n/100V" CAPC1608X08N 3037.5,1539.17 r270 top
C602 "220p/50V" CAPC1608X08N 5539.69,1575 r180 top
C603 "100n/100V" CAPC1608X08N 2725,1771.75 r90 top
C604 "100n/100V" CAPC1608X08N 2800,1771.75 r90 top
C605 "100n/100V" CAPC1608X08N 2875,1771.75 r90 top
C606 "100n/100V" CAPC1608X08N 2950,1771.75 r90 top
C607 "10n/100V" CAPC1608X08N 5432.15,1700 r270 top
C608 "220p/50V" CAPC1608X08N 5324.61,1575 r180 top
C609 "220p/50V" CAPC1608X08N 4914.69,1575 r180 top
C610 "10n/100V" CAPC1608X08N 4807.15,1700 r270 top
C611 "470n/50V" CAPC1608X08N 3125,2372.05 r270 top
C612 "220p/50V" CAPC1608X08N 4699.61,1575 r180 top
C613 "100n/100V" CAPC1608X08N 3025,1771.75 r90 top
C614 "22p/50V" CAPC1005X06N 4425,600 r180 top
C615 "22p/50V" CAPC1005X06N 4425,1250 r0 top
C616 "22p/50V" CAPC1005X06N 6083.66,837.5 r0 top
C617 "100n/100V" CAPC1608X08N 6050,1587.5 r270 top
C618 "22p/50V" CAPC1005X06N 5995.08,1675 r180 top
C700 "47n/100V" CAPC1608X08N 1512.5,3125 r0 top
C701 "47n/100V" CAPC1608X08N 1812.5,3125 r180 top
C702 "47n/100V" CAPC1608X08N 4762.5,3125 r180 top
C703 "47n/100V" CAPC1608X08N 4462.5,3125 r0 top
C800 "15u/100V" CAPC6153X67N 4837.5,2562.5 r180 top
C801 "15u/100V" CAPC6153X67N 4837.5,2325 r180 top
C802 "1u/100V" CAPC3225X25N 5500,2487.5 r180 top
C803 "1u/100V" CAPC3225X25N 5500,2362.5 r180 top
C804 "3u3/100V" CAPC4532X16N 5562.5,2712.5 r180 top
C805 "2n2/100V" CAPC1005X06N 5337.5,2246.26 r270 top
C806 "2u2/100V" CAPC3225X25N 5500,2237.5 r180 top
C807 "100n/100V" CAPC1608X08N 5485.24,2125 r180 top
C808 "2n2/100V" CAPC1005X06N 5000,2159.84 r270 top
C809 "100p/200V" CAPC1005X06N 5062.5,2197.64 r270 top
C810 "22u/6.3V" CAPC3216X18N 4912.5,2000 r0 top
C850 "100n/100V" CAPC1608X08N 2062.5,2946.46 r270 top
C851 "2u2/10V" CAPC2012X14N 2025,2587.5 r90 top
C852 "100n/100V" CAPC1608X08N 2165.75,2962.5 r180 top
C900 "100n/100V" CAPC1608X08N 1496.46,2490.75 r0 top
C920 "100n/100V" CAPC1608X08N 275,2725 r90 top
C921 "100n/100V" CAPC1608X08N 275,2850 r270 top
C922 "100n/100V" CAPC1608X08N 600,2875 r180 top
C923 "100n/100V" CAPC1608X08N 600,2512.5 r90 top
C924 "100n/100V" CAPC1608X08N 550,2375 r180 top
C925 "100n/100V" CAPC1608X08N 525,2975 r270 top
D600 "DFLS1100Q-7" PowerDI123 2637.5,1535.04 r270 top
D601 "DFLS1100Q-7" PowerDI123 3725,1575 r0 top
D602 "PTVS60VS1UR" NEXPERIA_PTVSxS1UR 2962.5,1612.5 r90 top
D603 "S1MSP1-7" S1MSP1 2837.5,1637.5 r0 top
D604 "PESD5V0V1BB" SOD523_PESD_NEXPERIA 5511.15,1687.5 r90 top
D605 "PESD5V0V1BB" SOD523_PESD_NEXPERIA 5353.15,1687.5 r90 top
D606 "PESD5V0V1BB" SOD523_PESD_NEXPERIA 4886.15,1687.5 r90 top
D607 "PESD5V0V1BB" SOD523_PESD_NEXPERIA 4728.15,1687.5 r90 top
D608 "DFLS1100Q-7" PowerDI123 4275,761.02 r90 top
D609 "PACDN042Y3R" ON-SEMI-SOT-23-3-CASE-318-08 4425,875 r270 top
D610 "PACDN042Y3R" ON-SEMI-SOT-23-3-CASE-318-08 5925,700 r270 top
enable_DCDC "Testpoint_Square" Testpoint_S1 4765.06,1987.5 r90 top
FD_LL "Comment" Fiducial_2 196.85,590.55 r0 top locked
FD_LR "Comment" Fiducial_2 6102.36,590.55 r0 top locked
FD_UR "Comment" Fiducial_2 6102.36,3011.81 r0 top locked
GND "Testpoint_Square" Testpoint_S1 4025,675 r90 top
IC920 "MCP9800A0T-M/OT" SOT-23-OT5_L 400,2962.5 r180 top
J300 "molex_microfit_3_12x2_THT" MOLEX_MICROFIT_12x2_THT 3445,200 r180 top
J301 "molex_microfit_3_01x2_THT" MOLEX_MICROFIT_01x2_THT 5350,200 r180 top
J302 "molex_microfit_3_01x2_THT" MOLEX_MICROFIT_01x2_THT 4975,200 r180 top
J303 "gen_pinheader_2.54_2x9" Pinheader_2.54_2x9 1425,2750 r0 top
J304 "molex_microfit_3_08x2_THT" MOLEX_MICROFIT_08x2_THT 2050,200 r180 top
J305 "molex_microfit_3_01x2_THT" MOLEX_MICROFIT_01x2_THT 5725,200 r180 top
J306 "molex_microfit_3_01x2_THT" MOLEX_MICROFIT_01x2_THT 4600,200 r180 top
J307 "molex_microfit_3_08x2_THT" MOLEX_MICROFIT_08x2_THT 900,200 r180 top
J308 "gen_pinheader_2.54_2x7" Pinheader_2.54_2x7 4525,2375 r90 top
J309 "gen_pinheader_2.54_2x7" Pinheader_2.54_2x7 6012.5,2375 r90 top
J310 "gen_pinheader_2.54_2" Pinheader_2.54_2 4050,1625 r90 top
J311 "gen_pinheader_2.54_2" Pinheader_2.54_2 4300,2625 r90 top
J312 "gen_pinheader_2.54_2" Pinheader_2.54_2 5787.5,2625 r90 top
L800 "470nH" SRP7028A 5200,2637.5 r0 top
L801 "47µH" TYS6045470M-10 5187.5,2025 r180 top
LD600 "green" LEDC1608X07N 2925,2850 r90 top
LD601 "green" LEDC1608X07N 2575,600 r180 top
LD800 "green" LEDC1608X07N 5600,2075 r180 top
LD850 "green" LEDC1608X07N 2287.5,2612.5 r180 top
MP_LL "Hole_3.2_Iso" Hole_3.2_Iso 196.85,196.85 r0 top locked
MP_LR "Hole_3.2_Iso" Hole_3.2_Iso 6102.36,196.85 r0 top locked
MP_UL "Hole_3.2_Iso" Hole_3.2_Iso 196.85,3740.16 r0 top locked
MP_UR "Hole_3.2_Iso" Hole_3.2_Iso 6102.36,3740.16 r0 top locked
Q600 "MJD31CAJ" NEXPERIA_DPAK_SOT428C 3412.01,2597.34 r0 top
Q601 "DMN10H220L-7" SOT95P237X110-3N 4425,1050 r270 top
Q602 "DMN10H220L-7" SOT95P237X110-3N 5850,1652.46 r180 top
R100 "0R" RESC1608X05N 1475,1652.56 r270 top
R200_1 "0R" RESC1608X05N 2550,775 r270 top (schematic designator R200)
R200_2 "0R" RESC1608X05N 1400,775 r90 top (schematic designator R200)
R201_1 "0R" RESC1608X05N 1637.01,1837.5 r90 top (schematic designator R201)
R201_2 "0R" RESC1608X05N 487.01,1837.5 r90 top (schematic designator R201)
R202_1 "0R" RESC1608X05N 1755,1837.5 r90 top (schematic designator R202)
R202_2 "0R" RESC1608X05N 605,1837.5 r90 top (schematic designator R202)
R203_1 "0R" RESC1608X05N 1755,887.5 r90 top (schematic designator R203)
R203_2 "0R" RESC1608X05N 605,887.5 r90 top (schematic designator R203)
R204_1 "0R" RESC1608X05N 1637.01,1687.5 r90 top (schematic designator R204)
R204_2 "0R" RESC1608X05N 487.01,1687.5 r90 top (schematic designator R204)
R205_1 "0R" RESC1608X05N 1755,1687.5 r90 top (schematic designator R205)
R205_2 "0R" RESC1608X05N 605,1687.5 r90 top (schematic designator R205)
R206_1 "10k" RESC1608X05N 1637.01,775 r270 top (schematic designator R206)
R206_2 "10k" RESC1608X05N 487.01,775 r270 top (schematic designator R206)
R207_1 "10k" RESC1608X05N 1872.99,775 r270 top (schematic designator R207)
R207_2 "10k" RESC1608X05N 722.99,775 r270 top (schematic designator R207)
R208_1 "10k" RESC1608X05N 2109.02,775 r270 top (schematic designator R208)
R208_2 "10k" RESC1608X05N 959.02,775 r270 top (schematic designator R208)
R209_1 "10k" RESC1608X05N 2345,775 r270 top (schematic designator R209)
R209_2 "10k" RESC1608X05N 1195,775 r270 top (schematic designator R209)
R210_1 "0R" RESC1608X05N 2462.99,1512.5 r90 top (schematic designator R210)
R210_2 "0R" RESC1608X05N 1312.99,1512.5 r90 top (schematic designator R210)
R211_1 "0R" RESC1608X05N 2345,1512.5 r90 top (schematic designator R211)
R211_2 "0R" RESC1608X05N 1195,1512.5 r90 top (schematic designator R211)
R212_1 "0R" RESC1608X05N 2225,1512.5 r90 top (schematic designator R212)
R212_2 "0R" RESC1608X05N 1075,1512.5 r90 top (schematic designator R212)
R213_1 "0R" RESC1608X05N 2109.02,1512.5 r90 top (schematic designator R213)
R213_2 "0R" RESC1608X05N 959.02,1512.5 r90 top (schematic designator R213)
R214_1 "0R" RESC1608X05N 1990.98,1512.5 r90 top (schematic designator R214)
R214_2 "0R" RESC1608X05N 840.98,1512.5 r90 top (schematic designator R214)
R215_1 "0R" RESC1608X05N 1872.99,1512.5 r90 top (schematic designator R215)
R215_2 "0R" RESC1608X05N 722.99,1512.5 r90 top (schematic designator R215)
R216_1 "0R" RESC1608X05N 1755,1512.5 r90 top (schematic designator R216)
R216_2 "0R" RESC1608X05N 605,1512.5 r90 top (schematic designator R216)
R217_1 "0R" RESC1608X05N 1637.01,1512.5 r90 top (schematic designator R217)
R217_2 "0R" RESC1608X05N 487.01,1512.5 r90 top (schematic designator R217)
R218_1 "10k" RESC1608X05N 1755,775 r270 top (schematic designator R218)
R218_2 "10k" RESC1608X05N 605,775 r270 top (schematic designator R218)
R219_1 "10k" RESC1608X05N 1990.98,775 r270 top (schematic designator R219)
R219_2 "10k" RESC1608X05N 840.98,775 r270 top (schematic designator R219)
R220_1 "10k" RESC1608X05N 2227.01,775 r270 top (schematic designator R220)
R220_2 "10k" RESC1608X05N 1077.01,775 r270 top (schematic designator R220)
R221_1 "10k" RESC1608X05N 2462.99,775 r270 top (schematic designator R221)
R221_2 "10k" RESC1608X05N 1312.99,775 r270 top (schematic designator R221)
R222_1 "1k" RESC1608X05N 2462.99,1225 r270 top (schematic designator R222)
R222_2 "1k" RESC1608X05N 1312.99,1225 r270 top (schematic designator R222)
R223_1 "1k" RESC1608X05N 2345,1225 r270 top (schematic designator R223)
R223_2 "1k" RESC1608X05N 1195,1225 r270 top (schematic designator R223)
R224_1 "1k" RESC1608X05N 2225,1225 r270 top (schematic designator R224)
R224_2 "1k" RESC1608X05N 1075,1225 r270 top (schematic designator R224)
R225_1 "1k" RESC1608X05N 2109.02,1225 r270 top (schematic designator R225)
R225_2 "1k" RESC1608X05N 959.02,1225 r270 top (schematic designator R225)
R226_1 "1k" RESC1608X05N 1990.98,1225 r270 top (schematic designator R226)
R226_2 "1k" RESC1608X05N 840.98,1225 r270 top (schematic designator R226)
R227_1 "1k" RESC1608X05N 1872.99,1225 r270 top (schematic designator R227)
R227_2 "1k" RESC1608X05N 722.99,1225 r270 top (schematic designator R227)
R228_1 "1k" RESC1608X05N 1755,1225 r270 top (schematic designator R228)
R228_2 "1k" RESC1608X05N 605,1225 r270 top (schematic designator R228)
R229_1 "1k" RESC1608X05N 1637.01,1225 r270 top (schematic designator R229)
R229_2 "1k" RESC1608X05N 487.01,1225 r270 top (schematic designator R229)
R230_1 "0R" RESC1608X05N 2487.5,1900 r0 top (schematic designator R230)
R230_2 "0R" RESC1608X05N 1337.5,1900 r0 top (schematic designator R230)
R231_1 "1k" RESC1608X05N 2525,1652.56 r270 top (schematic designator R231)
R231_2 "1k" RESC1608X05N 1375,1652.56 r270 top (schematic designator R231)
R232_1 "0R" RESC1608X05N 2330.31,1900 r180 top (schematic designator R232)
R232_2 "0R" RESC1608X05N 1180.31,1900 r180 top (schematic designator R232)
R400 "5k1" RESC1608X05N 2475,2200 r0 top
R401 "5k1" RESC1608X05N 2075,2150 r180 top
R500 "10k" RESC1608X05N 2725,1225 r270 top
R501 "10k" RESC1608X05N 3525,1225 r270 top
R502 "10k" RESC1608X05N 2825,1225 r270 top
R503 "10k" RESC1608X05N 3625,1225 r270 top
R504 "10k" RESC1608X05N 2925,1225 r270 top
R505 "10k" RESC1608X05N 3725,1225 r270 top
R506 "10k" RESC1608X05N 3025,1225 r270 top
R507 "10k" RESC1608X05N 3825,1225 r270 top
R508 "10k" RESC1608X05N 3125,1225 r270 top
R509 "10k" RESC1608X05N 3925,1225 r270 top
R510 "10k" RESC1608X05N 3225,1225 r270 top
R511 "10k" RESC1608X05N 4025,1225 r270 top
R512 "10k" RESC1608X05N 3325,1225 r270 top
R513 "10k" RESC1608X05N 4125,1225 r270 top
R514 "10k" RESC1608X05N 3425,1225 r270 top
R515 "10k" RESC1608X05N 3875,775 r270 top
R516 "0R" RESC1608X05N 3725,775 r270 top
R517 "0R" RESC1608X05N 3625,775 r270 top
R518 "0R" RESC1608X05N 3525,775 r270 top
R519 "0R" RESC1608X05N 3425,775 r270 top
R520 "0R" RESC1608X05N 3325,775 r270 top
R521 "0R" RESC1608X05N 3225,775 r270 top
R522 "0R" RESC1608X05N 3125,775 r270 top
R523 "0R" RESC1608X05N 3025,775 r270 top
R524 "0R" RESC1608X05N 2925,775 r270 top
R525 "0R" RESC1608X05N 2825,775 r270 top
R526 "0R" RESC1608X05N 2725,775 r270 top
R600 "10R" RESC2012X05N 2812.5,1510.63 r180 top
R601 "0R" RESC1608X05N 3403.13,2375 r0 top
R602 "0R" RESC1608X05N 3025,2925 r0 top
R603 "0R" RESC1608X05N 2575,537.5 r0 top
R604 "270R" RESC1608X05N 3025,2775 r180 top
R605 "2k7" RESC1608X05N 2675,572.44 r90 top
R606 "0R" RESC1608X05N 2737.5,2400 r0 top
R607 "0R" RESC1608X05N 2737.5,2462.5 r0 top
R608 "0R" RESC1608X05N 2737.5,2525 r0 top
R609 "0R" RESC1608X05N 2737.5,2587.5 r0 top
R610 "0R" RESC1608X05N 5511.15,850 r270 top
R611 "150R" RESC1608X05N 5432.15,1602.56 r270 top
R612 "0R" RESC1608X05N 5353.15,850 r270 top
R613 "0R" RESC1608X05N 2737.5,2775 r0 top
R614 "0R" RESC1608X05N 2737.5,2837.5 r0 top
R615 "0R" RESC1608X05N 2737.5,2650 r0 top
R616 "5k1" RESC1608X05N 2375,2600 r270 top
R617 "5k1" RESC1608X05N 2375,2762.5 r90 top
R618 "4R53" RESC1608X05N 3212.5,2371.06 r270 top
R619 "0R" RESC1608X05N 4886.15,850 r270 top
R620 "0R" RESC1608X05N 2737.5,2712.5 r0 top
R621 "150R" RESC1608X05N 4807.15,1602.56 r270 top
R622 "0R" RESC1608X05N 4800,812.5 r315 top
R623 "0R" RESC1608X05N 2900,2000 r180 top
R624 "0R" RESC1608X05N 2900,2062.5 r180 top
R625 "0R" RESC1608X05N 2900,2250 r180 top
R626 "0R" RESC1608X05N 2900,2312.5 r180 top
R627 "5k1" RESC1608X05N 2900,1862.5 r0 top
R628 "150R" RESC1608X05N 4375,700 r270 top
R629 "0R" RESC1608X05N 2737.5,1875 r0 top
R630 "0R" RESC1608X05N 2737.5,1937.5 r0 top
R631 "0R" RESC1608X05N 2737.5,2000 r0 top
R632 "150R" RESC1608X05N 4475,700 r270 top
R633 "0R" RESC1608X05N 2737.5,2062.5 r0 top
R634 "150R" RESC1608X05N 4475,1350 r270 top
R635 "0R" RESC1608X05N 2737.5,2125 r0 top
R636 "0R" RESC1608X05N 2737.5,2187.5 r0 top
R637 "0R" RESC1608X05N 3403.12,2300 r180 top
R638 "100k" RESC1608X05N 4425,1175 r180 top
R639 "0R" RESC1608X05N 2737.5,2250 r0 top
R640 "0R" RESC1608X05N 2737.5,2312.5 r0 top
R641 "5k1" RESC1608X05N 5725,1624.9 r90 top
R642 "150R" RESC1608X05N 5975,1587.5 r90 top
R643 "100k" RESC1608X05N 6002.56,1725 r0 top
R700 "10k" RESC1608X05N 1662.5,3050 r0 top
R701 "10k" RESC1608X05N 4612.5,3050 r180 top
R702 "10k" RESC1608X05N 1662.5,3125 r180 top
R703 "10k" RESC1608X05N 4612.5,3125 r0 top
R704 "10k NTC" RESC1005X04N 1587.5,3187.5 r90 top
R705 "10k NTC" RESC1005X04N 4687.5,3187.5 r90 top
R706 "ThermaWick" Vishay_THJP_0603 5862.5,3250 r270 top
R707 "ThermaWick" Vishay_THJP_0603 5087.5,3250 r270 top
R708 "ThermaWick" Vishay_THJP_0603 4312.5,3250 r270 top
R709 "ThermaWick" Vishay_THJP_0603 3537.5,3251.57 r270 top
R710 "ThermaWick" Vishay_THJP_0603 2762.5,3250 r270 top
R711 "ThermaWick" Vishay_THJP_0603 1987.5,3250 r270 top
R712 "ThermaWick" Vishay_THJP_0603 1212.5,3250 r270 top
R713 "ThermaWick" Vishay_THJP_0603 437.5,3250 r270 top
R714 "68R" RESC5025X07N 5675,3400 r0 top
R715 "68R" RESC5025X07N 5275,3750 r0 top
R716 "68R" RESC5025X07N 4900,3400 r0 top
R717 "68R" RESC5025X07N 4500,3750 r0 top
R718 "68R" RESC5025X07N 4125,3750 r0 top
R719 "68R" RESC5025X07N 3725,3750 r0 top
R720 "68R" RESC5025X07N 3350,3400 r0 top
R721 "68R" RESC5025X07N 2950,3400 r0 top
R722 "68R" RESC5025X07N 2575,3400 r0 top
R723 "68R" RESC5025X07N 2175,3400 r0 top
R724 "68R" RESC5025X07N 1800,3750 r0 top
R725 "68R" RESC5025X07N 1400,3400 r0 top
R726 "68R" RESC5025X07N 1025,3400 r0 top
R727 "68R" RESC5025X07N 625,3400 r180 top
R728 "68R" RESC5025X07N 5675,3750 r0 top
R729 "68R" RESC5025X07N 5275,3400 r0 top
R730 "68R" RESC5025X07N 4900,3750 r0 top
R731 "68R" RESC5025X07N 4500,3400 r0 top
R732 "68R" RESC5025X07N 4125,3400 r0 top
R733 "68R" RESC5025X07N 3725,3400 r0 top
R734 "68R" RESC5025X07N 3350,3750 r0 top
R735 "68R" RESC5025X07N 2950,3750 r0 top
R736 "68R" RESC5025X07N 2575,3750 r0 top
R737 "68R" RESC5025X07N 2175,3750 r0 top
R738 "68R" RESC5025X07N 1800,3400 r0 top
R739 "68R" RESC5025X07N 1400,3750 r0 top
R740 "68R" RESC5025X07N 1025,3750 r0 top
R741 "68R" RESC5025X07N 625,3750 r180 top
R800 "100R" RESC1608X05N 4712.5,2737.5 r270 top
R801 "0R" RESC1608X05N 5512.5,2037.5 r270 top
R802 "0R1" RESC2012X05N 5475,2587.5 r180 top
R803 "0R" RESC1608X05N 5200,2812.5 r0 top
R804 "240R" RESC1608X05N 5687.5,2037.5 r90 top
R805 "287k" RESC1608X05N 5387.5,2100 r90 top
R806 "174k" RESC1608X05N 4925,2112.5 r90 top
R807 "0R" RESC1608X05N 4737.5,2150 r0 top
R808 "100k" RESC1608X05N 4862.5,2112.5 r270 top
R809 "27k4" RESC1608X05N 5050,2342.22 r90 top
R810 "10k" RESC1608X05N 4737.5,2087.5 r180 top
R850 "0R" RESC1608X05N 2135.24,2539.79 r0 top
R851 "0R" RESC1608X05N 2262.5,2822.54 r270 top
R852 "1M" RESC1608X05N 2135.24,2600 r180 top
R853 "0R" RESC1608X05N 2287.5,2550 r0 top
R854 "240R" RESC1608X05N 2287.5,2675 r0 top
R900 "100k" RESC1608X05N 1067.42,2465.75 r0 top
R901 "100k" RESC1608X05N 1067.42,2278.25 r0 top
R902 "100k" RESC1608X05N 1067.42,2090.75 r0 top
R903 "100k" RESC1608X05N 1742.42,2228.25 r180 top
R904 "100k" RESC1608X05N 1742.42,2415.75 r180 top
R905 "100k" RESC1608X05N 1067.42,2403.25 r0 top
R906 "100k" RESC1608X05N 1067.42,2215.75 r0 top
R907 "100k" RESC1608X05N 1742.42,2103.25 r180 top
R908 "100k" RESC1608X05N 1742.42,2290.75 r180 top
R909 "100k" RESC1608X05N 1742.42,2478.25 r180 top
R910 "100k" RESC1608X05N 1067.42,2528.25 r0 top
R911 "100k" RESC1608X05N 1067.42,2340.75 r0 top
R912 "100k" RESC1608X05N 1067.42,2153.25 r0 top
R913 "100k" RESC1608X05N 1742.42,2165.75 r180 top
R914 "100k" RESC1608X05N 1742.42,2353.25 r180 top
R915 "100k" RESC1608X05N 1742.42,2540.75 r180 top
R916 "10k" RESC1608X05N 1312.4,2490.75 r180 top
R917 "100k" RESC1608X05N 904.92,2528.25 r0 top
R918 "100k" RESC1608X05N 904.92,2340.75 r0 top
R919 "100k" RESC1608X05N 904.92,2153.25 r0 top
R920 "10k" RESC1608X05N 600,2975 r270 top
R921 "100k" RESC1608X05N 1904.92,2165.75 r180 top
R922 "100k" RESC1608X05N 1904.92,2353.25 r180 top
R923 "100k" RESC1608X05N 1904.92,2540.75 r180 top
R924 "100k" RESC1608X05N 904.92,2465.75 r0 top
R925 "100k" RESC1608X05N 904.92,2278.25 r0 top
R926 "100k" RESC1608X05N 904.92,2090.75 r0 top
R927 "100k" RESC1608X05N 1904.92,2228.25 r180 top
R928 "100k" RESC1608X05N 1904.92,2415.75 r180 top
R929 "100k" RESC1608X05N 904.92,2403.25 r0 top
R930 "100k" RESC1608X05N 904.92,2215.75 r0 top
R931 "100k" RESC1608X05N 1904.92,2103.25 r180 top
R932 "100k" RESC1608X05N 1904.92,2290.75 r180 top
R933 "100k" RESC1608X05N 1904.92,2478.25 r180 top
T600 "HM2102NLT" HM2102NL 5550,1225 r90 top
T601 "HM2102NLT" HM2102NL 4925,1225 r90 top
TPL_H_N "Testpoint_Square" Testpoint_S1 5285.1,1772.24 r90 top
TPL_H_P "Testpoint_Square" Testpoint_S1 5579.2,1772.24 r90 top
TPL_L_N "Testpoint_Square" Testpoint_S1 4660.1,1772.24 r90 top
TPL_L_P "Testpoint_Square" Testpoint_S1 4954.2,1772.24 r90 top
U200_1 "ADR4540BRZ" SOIC127P600X175-8N 1475,1100 r90 top (schematic designator U200)
U200_2 "ADR4540BRZ" SOIC127P600X175-8N 325,1100 r90 top (schematic designator U200)
U201_1 "ADG728BRUZ" ADI-RU-16_M 2050,1775 r180 top (schematic designator U201)
U201_2 "ADG728BRUZ" ADI-RU-16_M 900,1775 r180 top (schematic designator U201)
U202_1 "AD8628ARTZ-R2" ADI-RJ-5_M 2350,1787.5 r180 top (schematic designator U202)
U202_2 "AD8628ARTZ-R2" ADI-RJ-5_M 1200,1787.5 r180 top (schematic designator U202)
U400 "M24M02-DWMN3TP/K" SOIC127P600X175-8N 2275,2175 r0 top
U600 "MC33775A" NXP_SOT1510-2 3382.97,1888.88 r90 top
U601 "ACFL-6211T-000E" Broadcom_ACFL-6211T 6025,1150 r270 top
U800 "LM5163-Q1" R-PDSO-G8 5200,2325 r270 top
U850 "TPS7A1633AQDGNRQ1" TPS7A16A-Q1 2150,2762.5 r90 top
U851 "TPS7A1633DRBR" TPS7A16_VSON 2000.89,2762.5 r90 top
U900 "TCA9539PWR" PW0024A_M 1404.92,2265.75 r0 top
U920 "BME280" BOSC-BME280-8_V 400,2775 r0 top
U921 "SHT35-DIS-F" SHT3X 600,2775 r180 top
U922 "BME680" BME680 475,2512.5 r0 top
Vaux "Testpoint_Square" Testpoint_S1 2575,650 r90 top
Vbat "Testpoint_Square" Testpoint_S1 3150,1510.63 r90 top
Vbat_con_ext "Testpoint_Square" Testpoint_S1 3150,1575 r90 top
Vddc "Testpoint_Square" Testpoint_S1 3000,2850 r90 top
Vin_DCDC "Testpoint_Square" Testpoint_S1 4975,2775 r90 top
Vmodule "Testpoint_Square" Testpoint_S1 4025,802.56 r90 top

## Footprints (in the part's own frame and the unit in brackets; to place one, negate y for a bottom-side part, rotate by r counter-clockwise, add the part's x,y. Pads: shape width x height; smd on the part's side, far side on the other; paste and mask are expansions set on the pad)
ADI-RJ-5_M [mm] "SOT-23, 5-Leads, Body 2.9x1.6mm, Pitch 0.95mm, IPC Low Density"
  rect 1.3x0.7 smd: 1(-1.2,0.95) 2(-1.2,0) 3(-1.2,-0.95) 4(1.2,-0.95) 5(1.2,0.95)
  silkscreen extent -1.33,-1.5 0.15,1.97, body extent -0.85,-1.5 0.85,1.5, height 1.45
ADI-RU-16_M [mm] "SOP, 16-Leads, Body 5x4.4mm, Pitch 0.65mm, IPC Low Density"
  oval 1.85x0.35 smd: 1(-2.925,2.275) 2(-2.925,1.625) 3(-2.925,0.975) 4(-2.925,0.325) 5(-2.925,-0.325) 6(-2.925,-0.975) 7(-2.925,-1.625) 8(-2.925,-2.275) 9(2.925,-2.275) 10(2.925,-1.625) 11(2.925,-0.975) 12(2.925,-0.325) 13(2.925,0.325) 14(2.925,0.975) 15(2.925,1.625) 16(2.925,2.275)
  silkscreen extent -3.05,-2.55 1.6,3.12, body extent -2.25,-2.55 2.25,2.55, height 1.2
BME680 [mm] "Bosch BME680"
  rect 0.4x0.4 smd: 1(1.2,-1.2) 2(0.4,-1.2) 3(-0.4,-1.2) 4(-1.2,-1.2) 5(-1.2,1.2) 6(-0.4,1.2) 7(0.4,1.2) 8(1.2,1.2)
  silkscreen extent -1.68,-1.67 1.68,1.68, body extent -1.5,-1.5 1.5,1.5, height 1.02
BOSC-BME280-8_V [mm] "SMD, 8-Leads, Body 2.5x2.5mm, Pitch 0.65mm"
  rect 0.5x0.35 smd: 1(1.025,0.975) 2(1.025,0.325) 3(1.025,-0.325) 4(1.025,-0.975) 5(-1.025,-0.975) 6(-1.025,-0.325) 7(-1.025,0.325) 8(-1.025,0.975)
  silkscreen extent -0.39,-1.25 1.73,1.25, body extent -1.25,-1.25 1.25,1.25, height 1
Broadcom_ACFL-6211T [mm] "SOP, 12-Leads, Body 5,89x7,56mm, Pitch 0,80mm, IPC Medium Density"
  oval 1.8x0.6 smd: 1(-4.775,2) 2(-4.775,1.2) 3(-4.775,0.4) 4(-4.775,-0.4) 5(-4.775,-1.2) 6(-4.775,-2) 7(4.775,-2) 8(4.775,-1.2) 9(4.775,-0.4) 10(4.775,0.4) 11(4.775,1.2) 12(4.775,2)
  silkscreen extent -4.9,-2.95 3.47,2.98, body extent -5.19,-2.95 5.19,2.95, height 3.31
CAPC1005X06N [mm] "Chip Capacitor, 2-Leads, Body 1,00x0,50mm, IPC Medium Density"
  rrect50% 0.52x0.62 smd: 1(-0.51,0) 2(0.51,0)
  body extent -0.53,-0.28 0.53,0.28, height 0.55
CAPC1608X08N [mm] "Chip Capacitor, 2-Leads, Body 1,60x0,80mm, IPC Medium Density"
  rrect50% 0.75x0.95 smd: 1(-0.725,0) 2(0.725,0)
  body extent -0.85,-0.45 0.85,0.45, height 0.8
CAPC2012X14N [mm] "Chip Capacitor, 2-Leads, Body 2,00x1,25mm, IPC Medium Density"
  rrect40% 0.9x1.45 smd: 1(-1.025,0) 2(1.025,0)
  silkscreen extent -0.2,-0.63 0.2,0.63, body extent -1.1,-0.72 1.1,0.72, height 1.45
CAPC3216X18N [mm] "Chip Capacitor, 2-Leads, Body 3,20x1,60mm, IPC Medium Density"
  rrect30% 1.35x1.8 smd: 1(-1.375,0) 2(1.375,0)
  silkscreen extent -0.3,-0.8 0.3,0.8, body extent -1.7,-0.9 1.7,0.9, height 1.8
CAPC3225X25N [mm] "Chip Capacitor, 2-Leads, Body 3,20x2,50mm, IPC Medium Density"
  rrect30% 1.3x2.7 smd: 1(-1.4,0) 2(1.4,0)
  silkscreen extent -0.35,-1.25 0.35,1.25, body extent -1.7,-1.35 1.7,1.35, height 2.5
CAPC4532X16N [mm] "Chip Capacitor, 2-Leads, Body 4,50x3,20mm, IPC Medium Density"
  rect 1.6x3.5 smd: 1(-1.95,0) 2(1.95,0)
  silkscreen extent -0.75,-1.65 0.75,1.65, body extent -2.4,-1.75 2.4,1.75, height 1.55
CAPC6153X67N [mm] "Chip Capacitor, 2-Leads, Body 6,10x5,30mm, IPC Medium Density"
  rect 2.15x5.5 smd: 1(-2.525,0) 2(2.525,0)
  silkscreen extent -1.05,-2.65 1.05,2.65, body extent -3.25,-2.75 3.25,2.75, height 6.7
Fiducial_2 [mm] "Fiducial Round 1mm"
  round 1 smd paste-0.5 mask+0.5: 0(0,0)
  Top Copper keep-out circle w0.2: c0,0 r0.9
HM2102NL [mil]
  rect 67.5x40 smd: 1(-271.65,196.85)
  rrect50% 67.5x40 smd: 2(-271.65,117.85) 3(-271.65,38.85) 4(-271.65,-40.15) 5(-271.65,-119.15) 6(-271.65,-198.15) 7(270.85,-198.15) 8(270.85,-119.15) 9(270.85,-40.15) 10(270.85,38.85) 11(270.85,117.85) 12(270.85,196.85)
  silkscreen extent -224,-300 224,299, body extent -224,-299 224,299, height 197
Hole_3.2_Iso [mm]
  round 3.2 hole 3.2 unplated: Hole_3.2_Iso(0,0)
  Keep-Out Layer circle w1: c0,0 r2.3
  silkscreen extent -2.75,-2.75 2.75,2.75
LEDC1608X07N [mm] "LED, 2-Leads, Body 1,60x0,80mm, IPC Medium Density"
  rrect50% 0.7x0.9 smd: 1(-0.7,0) 2(0.7,0)
  silkscreen extent -1.35,0.35 -1.25,0.45, body extent -0.8,-0.4 0.8,0.4, height 0.7
MOLEX_MICROFIT_01x2_THT [mil] "Micro-Fit 3.0 Right Angle Header, 3.00mm Pitch, Dual Row, 2 Circuits, with Snap-in Plastic Peg PCB Lock, Tin, Glow Wire Capable, Black, 43045-0200"
  round 60 hole 40: 1(0,-170) 2(0,-287.99)
  round 39.37 hole 117.99 unplated paste-99999 mask+4: ""(0,0)
  silkscreen extent -125,-209 125,-209, body extent -141,-301 141,181, height 345
MOLEX_MICROFIT_08x2_THT [mil] "Micro-Fit 3.0 Right Angle Header, 3.00mm Pitch, Dual Row, 16 Circuits, with Snap-in Plastic Peg PCB Lock, Tin, Glow Wire Capable, Black, 43045-1600"
  round 60 hole 40: 1(-412.99,-170) 2(-295,-170) 3(-177.01,-170) 4(-59.02,-170) 5(59.02,-170) 6(177.01,-170) 7(295,-170) 8(412.99,-170) 9(-412.99,-287.99) 10(-295,-287.99) 11(-177.01,-287.99) 12(-59.02,-287.99) 13(59.02,-287.99) 14(177.01,-287.99) 15(295,-287.99) 16(412.99,-287.99)
  round 39.37 hole 117.99 unplated paste-99999 mask+4: ""(-328.5,0) ""(328.5,0)
  silkscreen extent -551,-209 551,85, body extent -554,-301 554,181, height 345
MOLEX_MICROFIT_12x2_THT [mil] "Micro-Fit 3.0 Right Angle Header, 3.00mm Pitch, Dual Row, 24 Circuits, with Snap-in Plastic Peg PCB Lock, Tin, Glow Wire Capable, Black, 43045-2400"
  round 60 hole 40: 1(-649.49,-170) 2(-530.98,-170) 3(-412.99,-170) 4(-295,-170) 5(-177.01,-170) 6(-59.02,-170) 7(59.02,-170) 8(177.01,-170) 9(295,-170) 10(412.99,-170) 11(530.98,-170) 12(649.49,-170) 13(-649.49,-287.99) 14(-530.98,-287.99) 15(-412.99,-287.99) 16(-295,-287.99) 17(-177.01,-287.99) 18(-59.02,-287.99) 19(59.02,-287.99) 20(177.01,-287.99) 21(295,-287.99) 22(412.99,-287.99) 23(530.98,-287.99) 24(649.49,-287.99)
  round 39.37 hole 117.99 unplated paste-99999 mask+4: ""(-565,0) ""(565,0)
  silkscreen extent -789,-209 790,85, body extent -790,-301 790,181, height 345
NEXPERIA_DPAK_SOT428C [mm] "D-PAK, 3-Pads, Body 6,21x6,73mm (max), IPC Medium Density"
  rect 2.4x1.4 smd paste-10: 1(-4.75,2.29) 3(-4.75,-2.29)
  rect 1.4x2.4 smd paste-10: 2(0,0)
  rect 5.75x5.9 smd paste-10: 4(1.675,0)
  silkscreen extent -4.87,-3.35 -1.6,3.66, body extent -5.89,-3.37 4.11,3.38, height 2.38
NEXPERIA_PTVSxS1UR [mm] "SODFL, 2-Leads, Body 1,70x3,50mm, IPC Medium Density"
  rect 1.2x1.2 smd: 1(-1.4,0) 2(1.4,0)
  silkscreen extent -1.95,0.85 -1.85,0.95, body extent -1.75,-0.95 1.75,0.95, height 1.1
NXP_SOT1510-2 [mm] "TSQFP, 64-Leads, Body 10,00x10,00mm, Pitch 0,50mm, Thermal Pad 7,00x7,00mm, IPC Medium Density"
  oval 1.5x0.27 smd: 1(-5.75,3.75) 2(-5.75,3.25) 3(-5.75,2.75) 4(-5.75,2.25) 5(-5.75,1.75) 6(-5.75,1.25) 7(-5.75,0.75) 8(-5.75,0.25) 9(-5.75,-0.25) 10(-5.75,-0.75) 11(-5.75,-1.25) 12(-5.75,-1.75) 13(-5.75,-2.25) 14(-5.75,-2.75) 15(-5.75,-3.25) 16(-5.75,-3.75) 33(5.75,-3.75) 34(5.75,-3.25) 35(5.75,-2.75) 36(5.75,-2.25) 37(5.75,-1.75) 38(5.75,-1.25) 39(5.75,-0.75) 40(5.75,-0.25) 41(5.75,0.25) 42(5.75,0.75) 43(5.75,1.25) 44(5.75,1.75) 45(5.75,2.25) 46(5.75,2.75) 47(5.75,3.25) 48(5.75,3.75)
  oval 0.27x1.5 smd: 17(-3.75,-5.75) 18(-3.25,-5.75) 19(-2.75,-5.75) 20(-2.25,-5.75) 21(-1.75,-5.75) 22(-1.25,-5.75) 23(-0.75,-5.75) 24(-0.25,-5.75) 25(0.25,-5.75) 26(0.75,-5.75) 27(1.25,-5.75) 28(1.75,-5.75) 29(2.25,-5.75) 30(2.75,-5.75) 31(3.25,-5.75) 32(3.75,-5.75) 49(3.75,5.75) 50(3.25,5.75) 51(2.75,5.75) 52(2.25,5.75) 53(1.75,5.75) 54(1.25,5.75) 55(0.75,5.75) 56(0.25,5.75) 57(-0.25,5.75) 58(-0.75,5.75) 59(-1.25,5.75) 60(-1.75,5.75) 61(-2.25,5.75) 62(-2.75,5.75) 63(-3.25,5.75) 64(-3.75,5.75)
  rect 7x7 smd: 65(0,0)
  silkscreen extent -5.87,-4.6 4.6,4.6, body extent -6,-6 6,6, height 1.6
ON-SEMI-SOT-23-3-CASE-318-08 [mm] "SOT23, 3-Leads, Body 2,92x2,37mm, Pitch 0,95mm, IPC Medium Density"
  rect 1x0.6 smd: 1(-1.2,0.95) 2(-1.2,-0.95) 3(1.2,0)
  silkscreen extent -1.32,-1.5 0.7,1.93, body extent -1.32,-1.52 1.32,1.52, height 1.11
Pinheader_2.54_2 [mm] "Pinheader, 2.54mm, gerade"
  round 1.75 hole 1: 1(-1.27,0) 2(1.27,0)
  silkscreen extent -2.47,-1.2 2.47,1.2, body extent -2.54,-1.27 2.54,1.27, height 8.74
Pinheader_2.54_2x7 [mm] "Pinheader, 2.54mm, gerade, 2-reihig"
  round 1.75 hole 1: 1(-7.62,-1.27) 2(-7.62,1.27) 3(-5.08,-1.27) 4(-5.08,1.27) 5(-2.54,-1.27) 6(-2.54,1.27) 7(0,-1.27) 8(0,1.27) 9(2.54,-1.27) 10(2.54,1.27) 11(5.08,-1.27) 12(5.08,1.27) 13(7.62,-1.27) 14(7.62,1.27)
  silkscreen extent -8.82,-2.47 8.82,2.47, body extent -8.89,-2.54 8.89,2.54, height 8.74
Pinheader_2.54_2x9 [mm] "Pinheader, 2.54mm, gerade, 2-reihig"
  round 1.75 hole 1: 1(-10.16,-1.27) 2(-10.16,1.27) 3(-7.62,-1.27) 4(-7.62,1.27) 5(-5.08,-1.27) 6(-5.08,1.27) 7(-2.54,-1.27) 8(-2.54,1.27) 9(0,-1.27) 10(0,1.27) 11(2.54,-1.27) 12(2.54,1.27) 13(5.08,-1.27) 14(5.08,1.27) 15(7.62,-1.27) 16(7.62,1.27) 17(10.16,-1.27) 18(10.16,1.27)
  silkscreen extent -11.43,-2.47 11.43,2.47, body extent -11.43,-2.54 11.43,2.54, height 8.74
